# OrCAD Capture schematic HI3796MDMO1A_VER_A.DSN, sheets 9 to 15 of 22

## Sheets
9 SHEET_09: size Custom
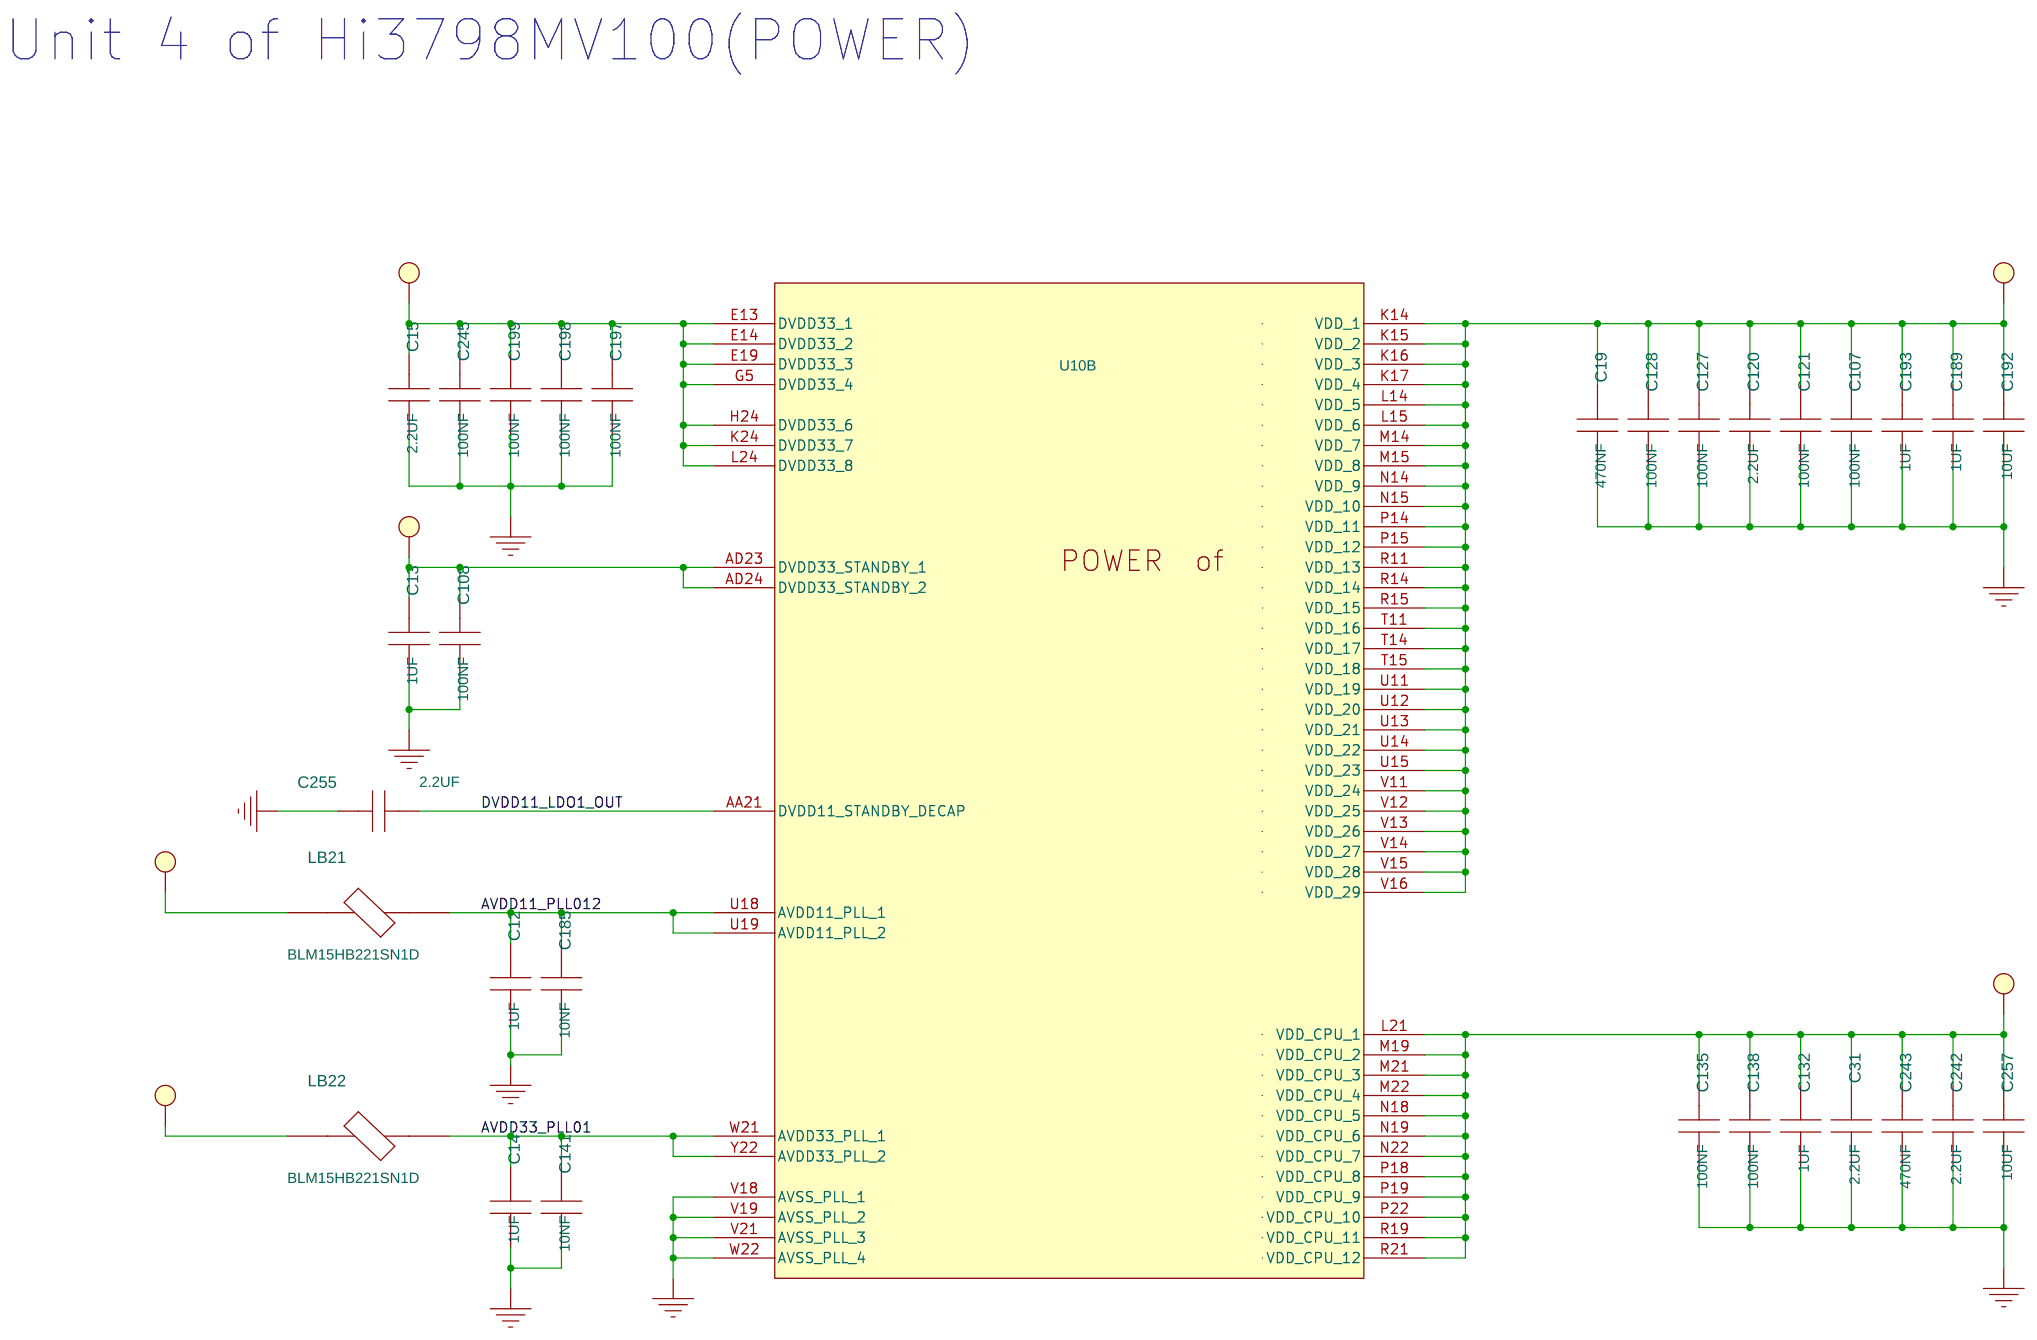
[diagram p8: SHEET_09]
10 SHEET_10: size B
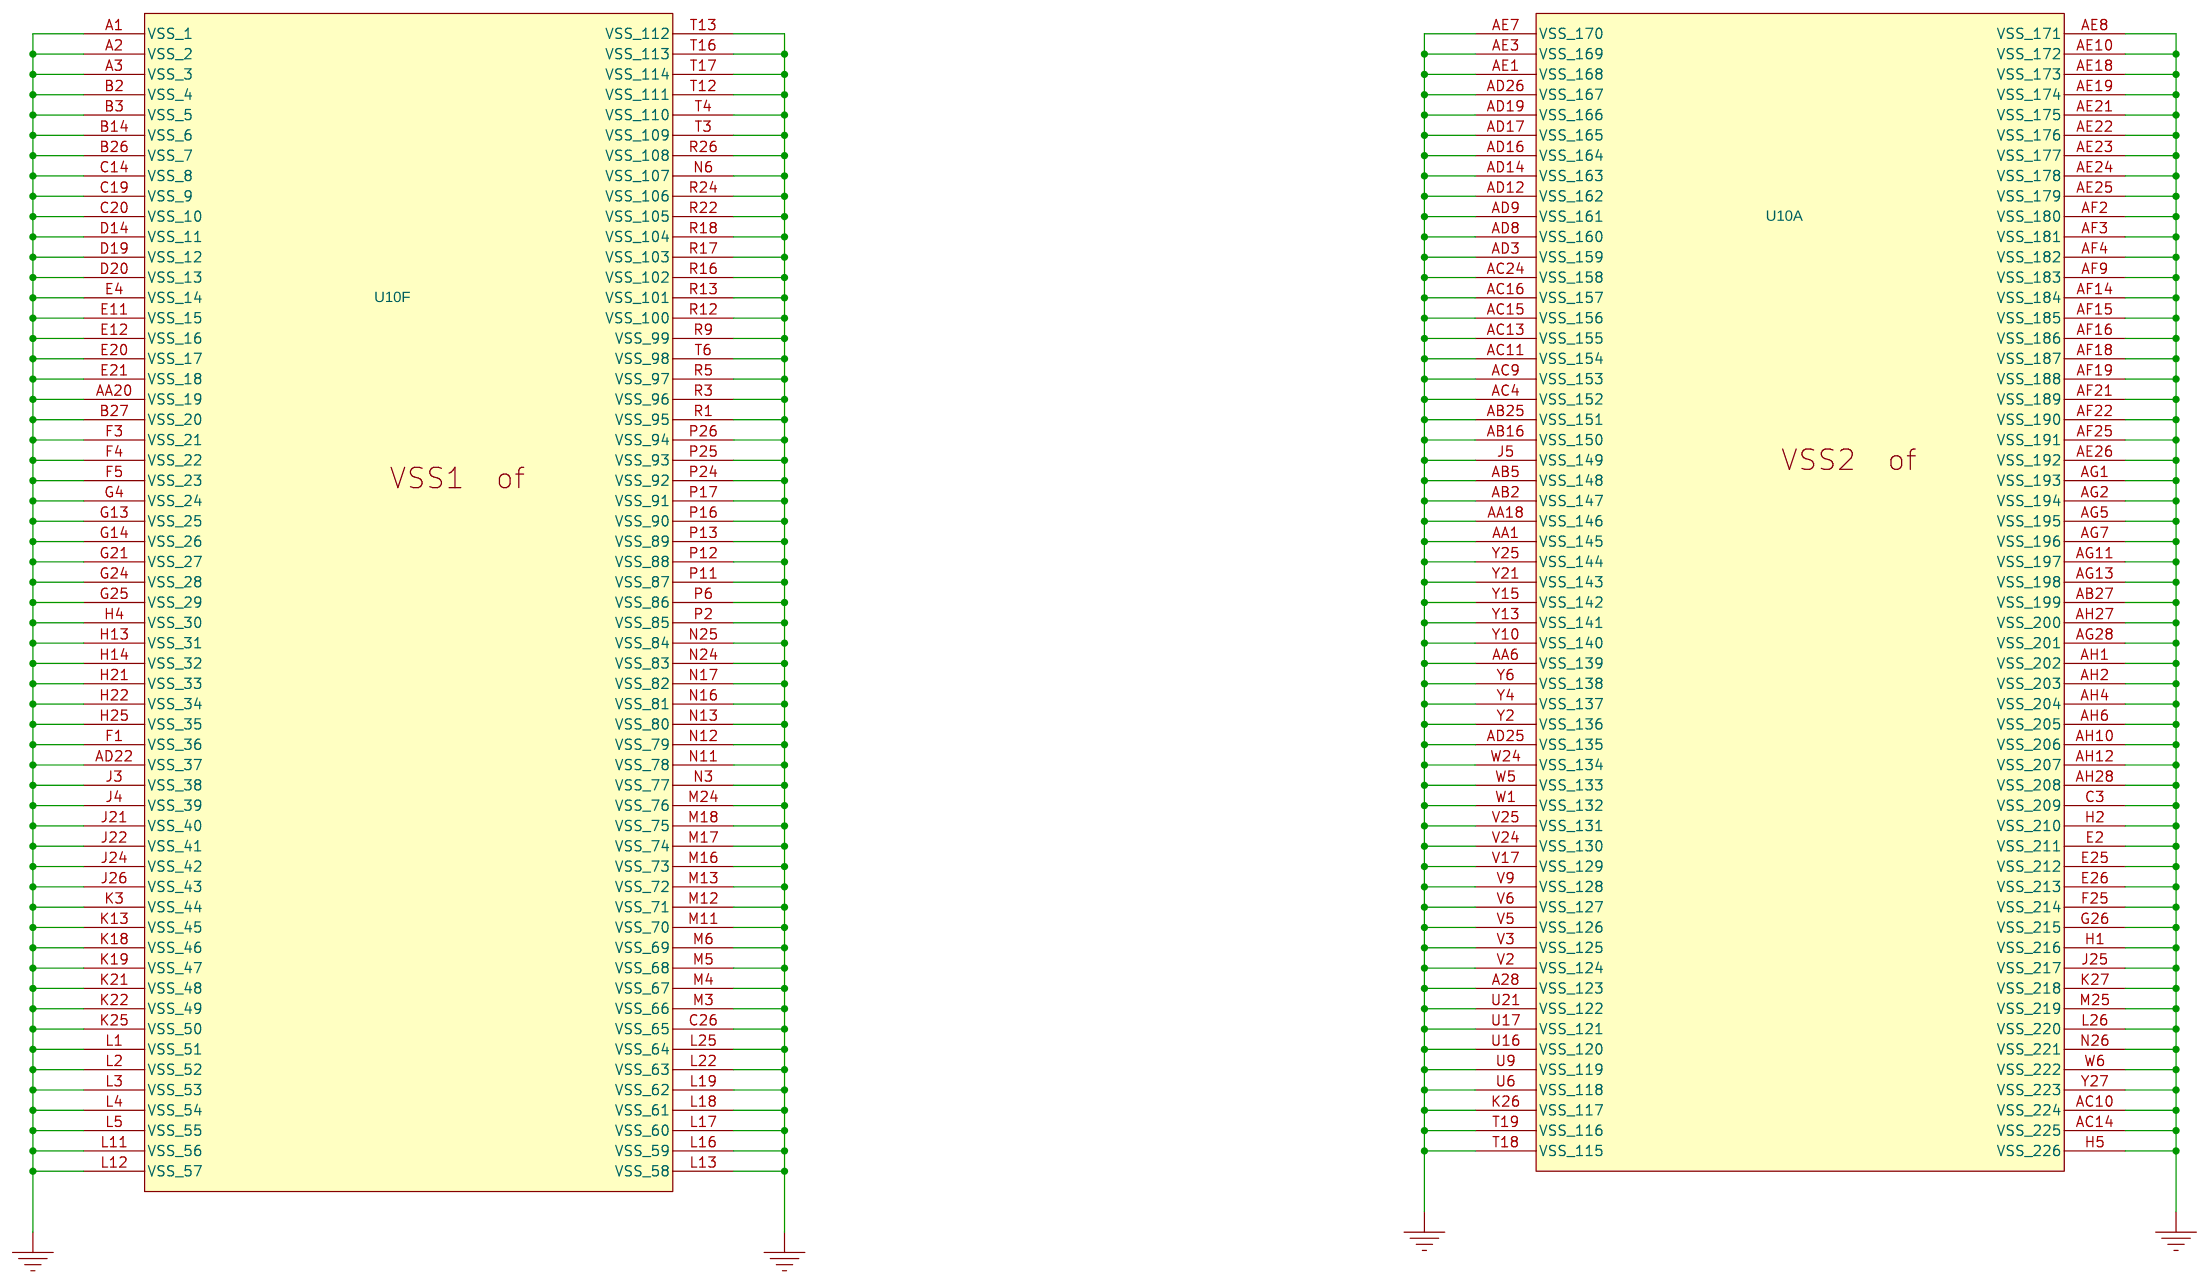
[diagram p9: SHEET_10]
11 SHEET_11: size Custom
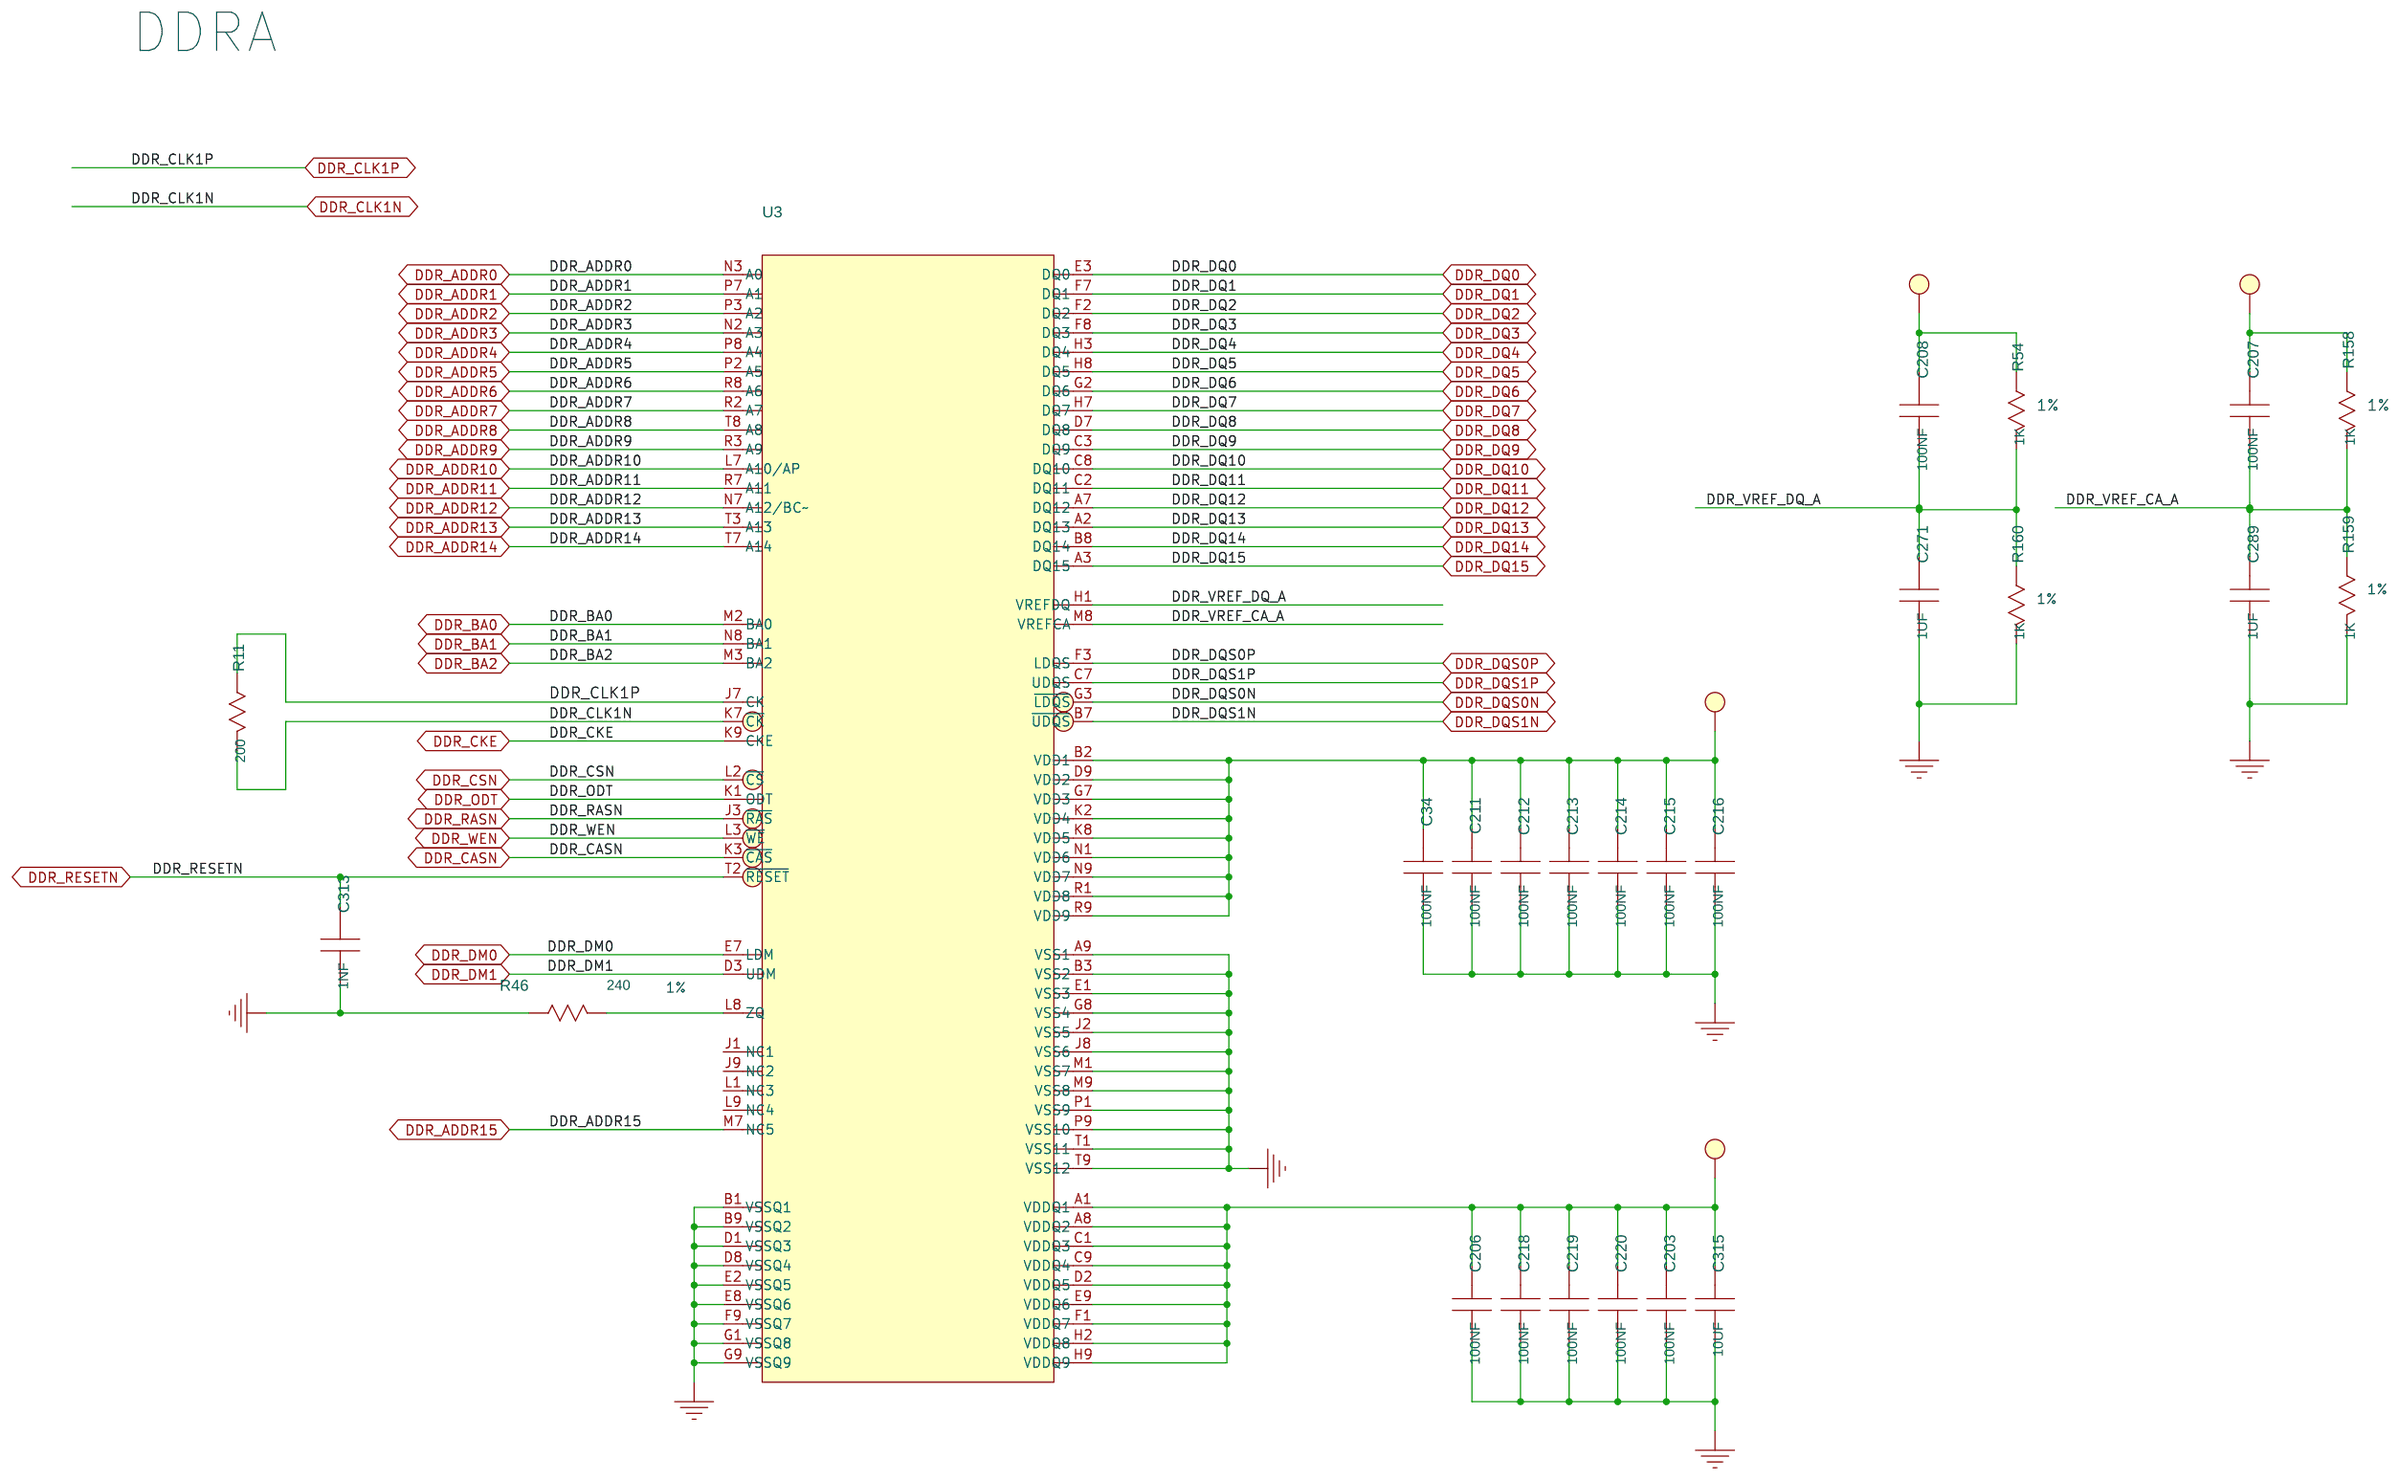
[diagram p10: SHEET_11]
12 SHEET_12: size B
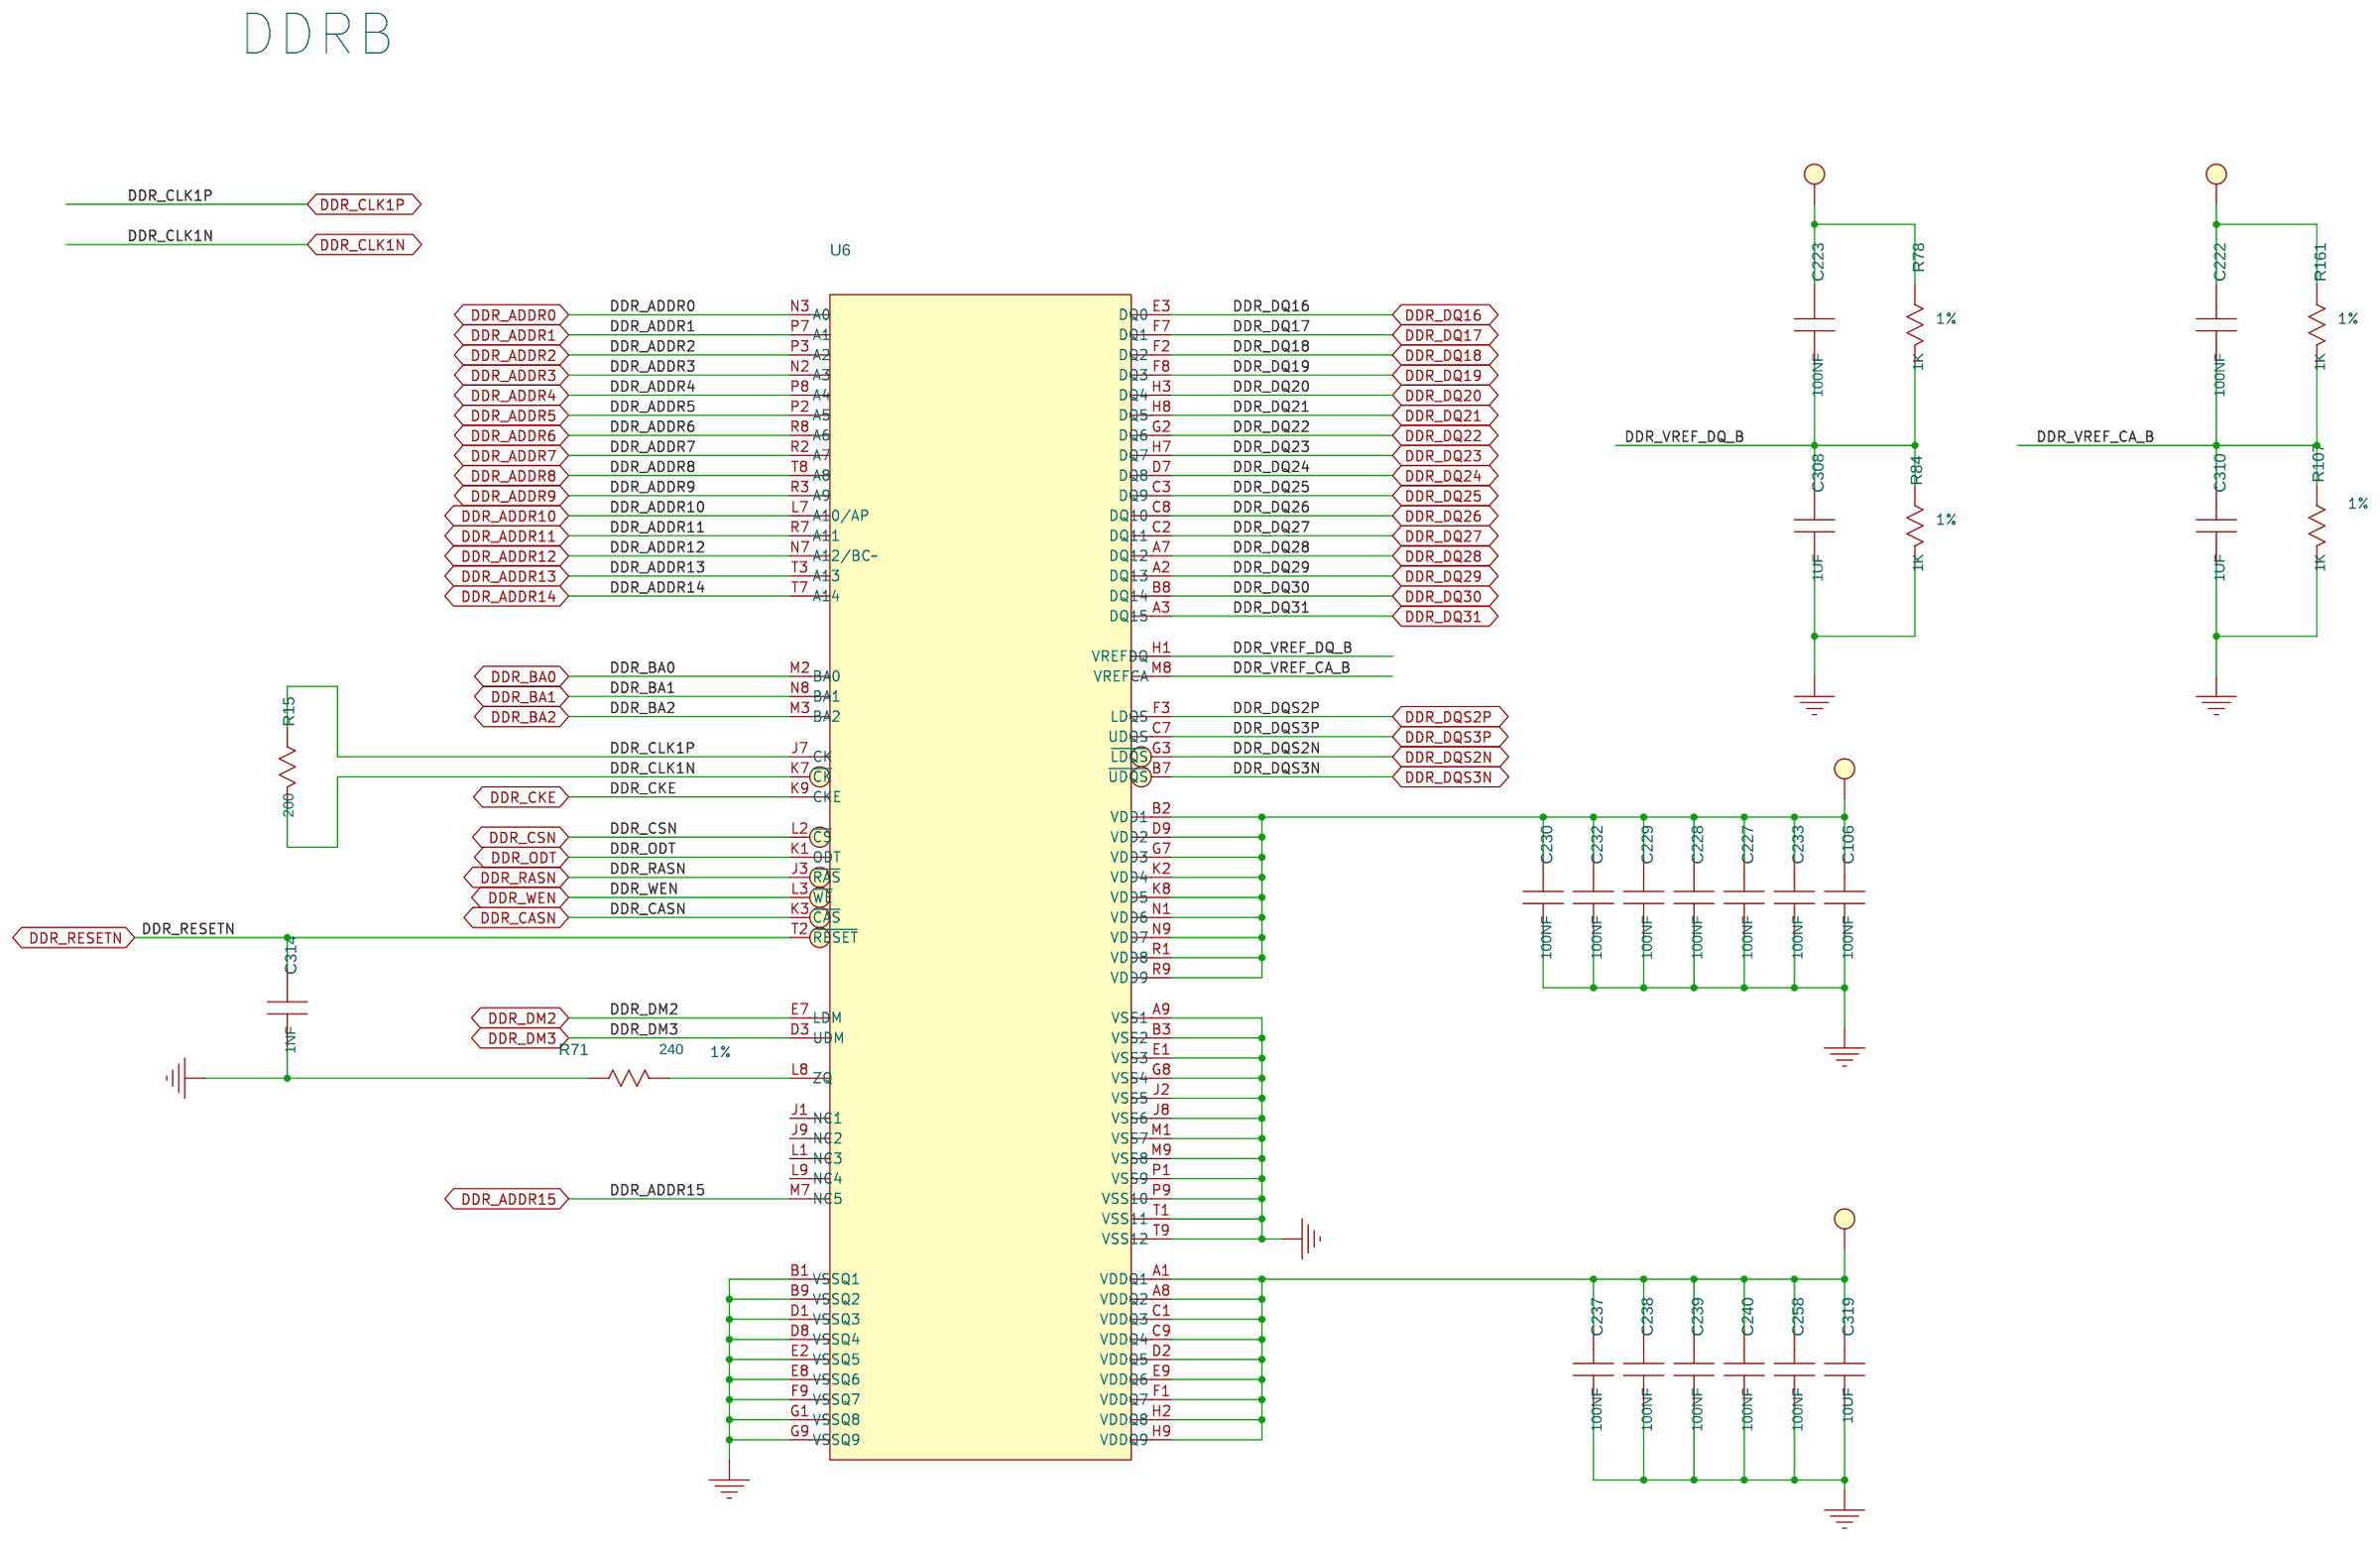
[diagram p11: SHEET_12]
13 SHEET_13: size Custom
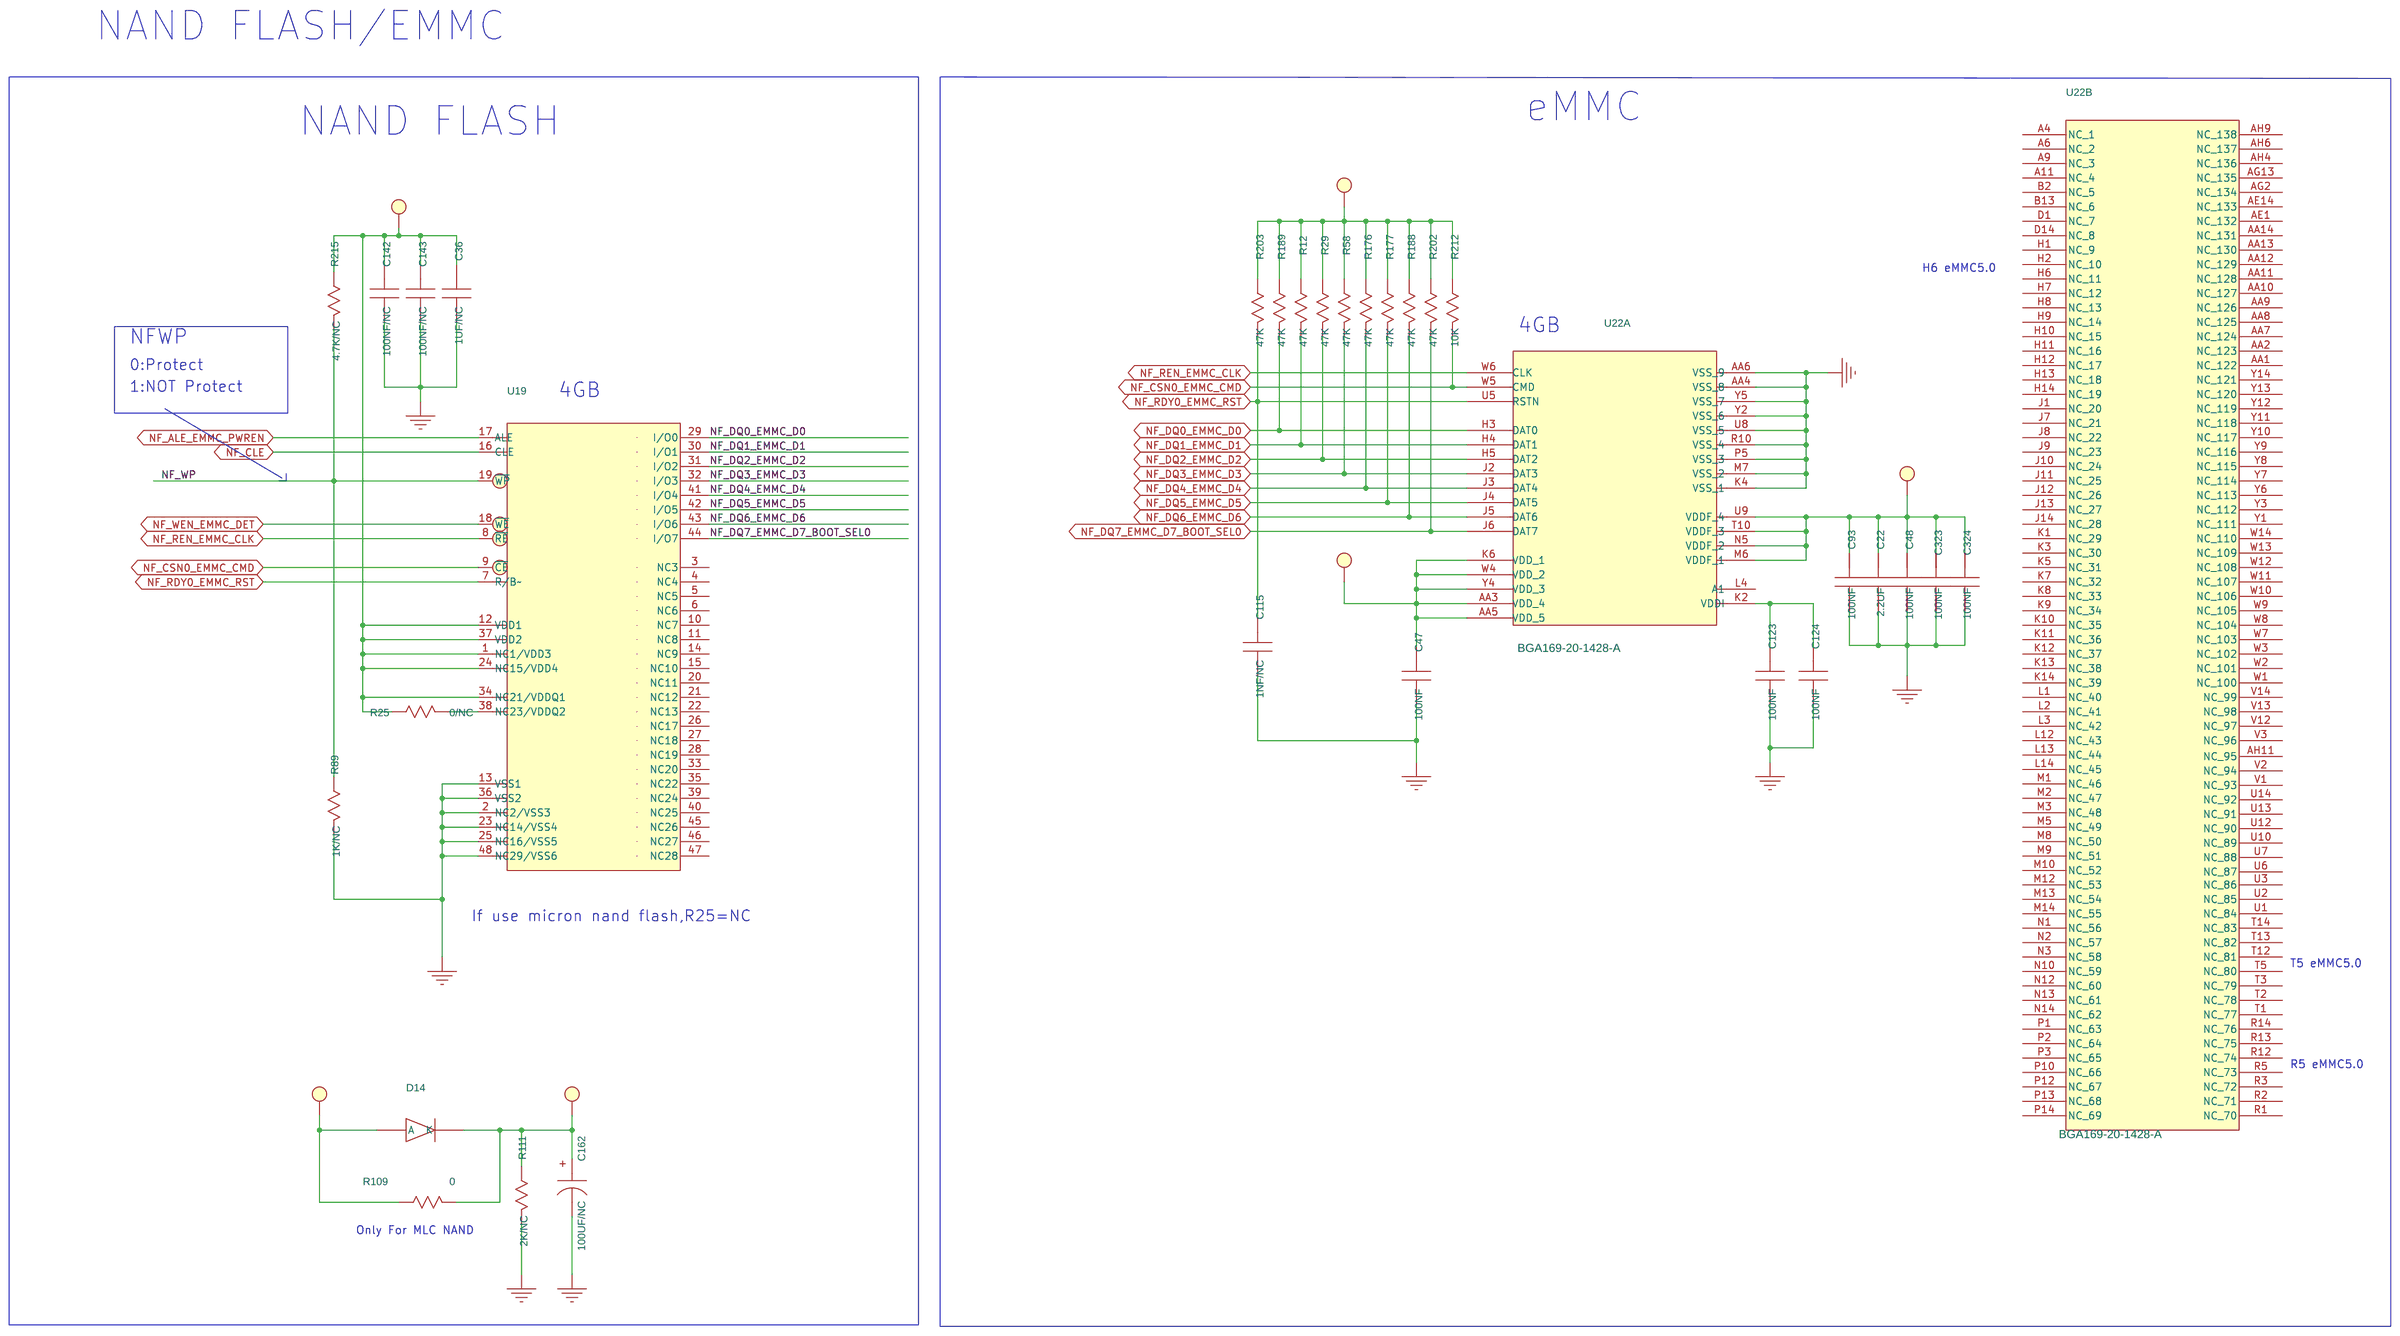
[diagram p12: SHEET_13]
14 SHEET_14: size Custom
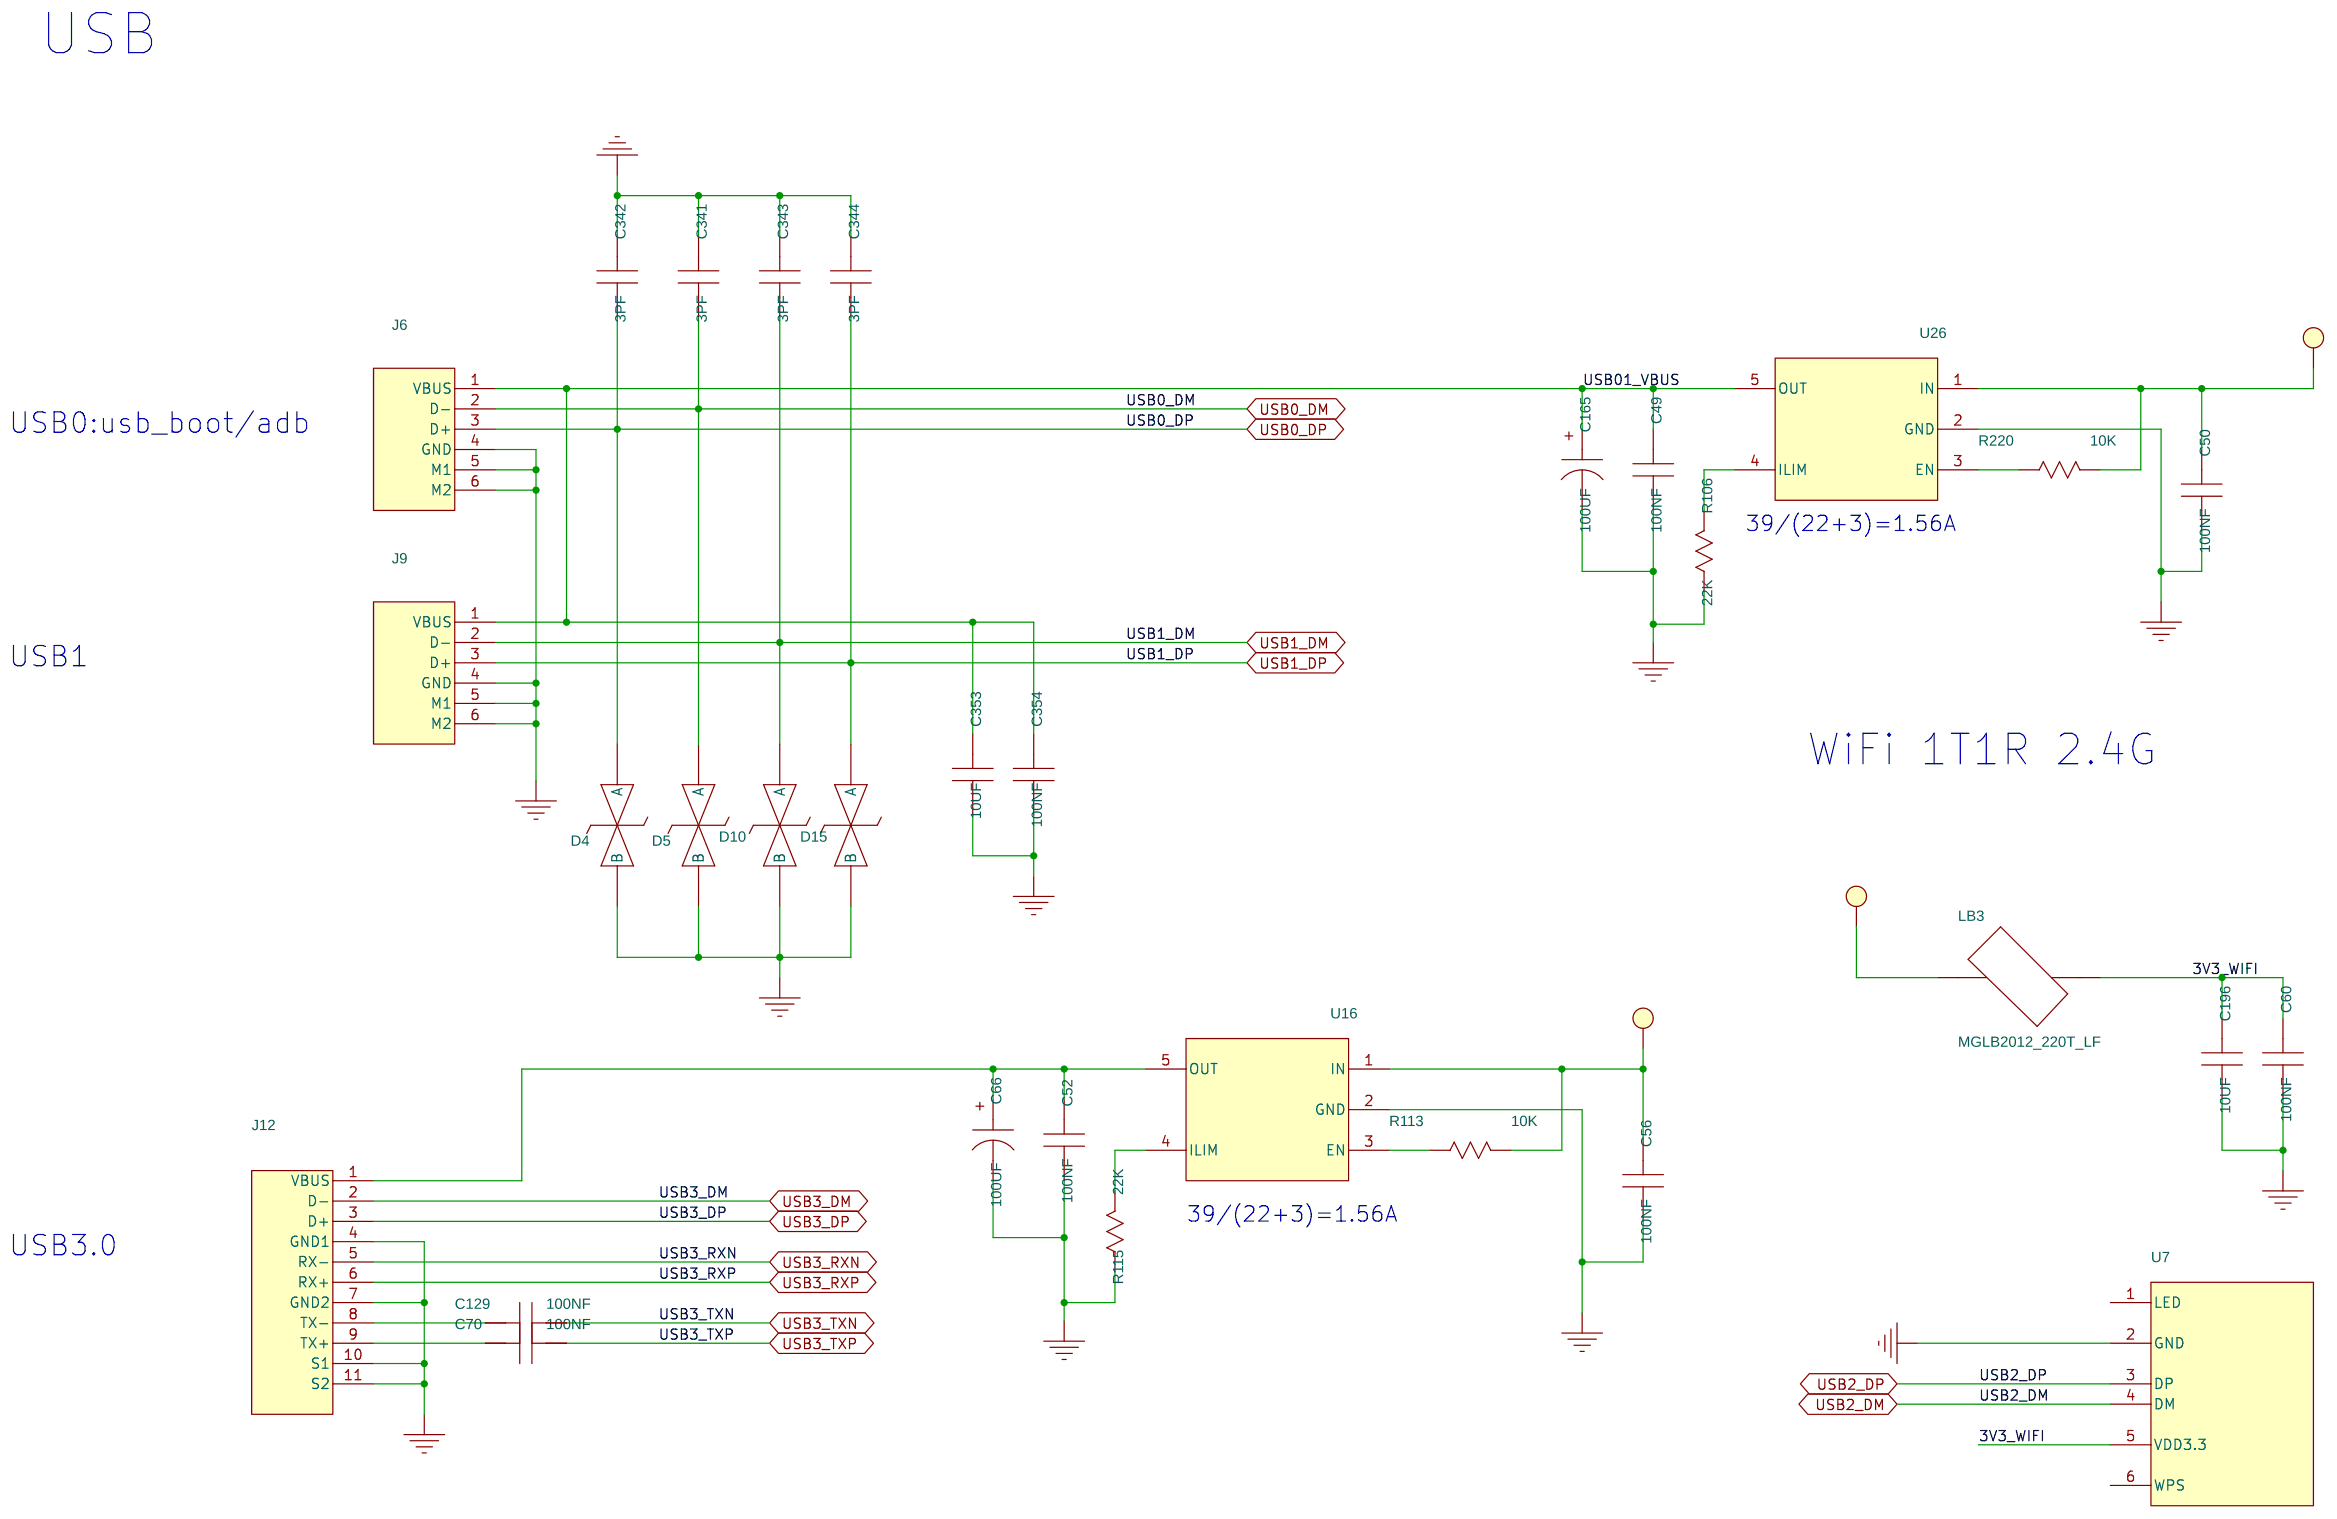
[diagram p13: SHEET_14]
15 SHEET_15: size Custom
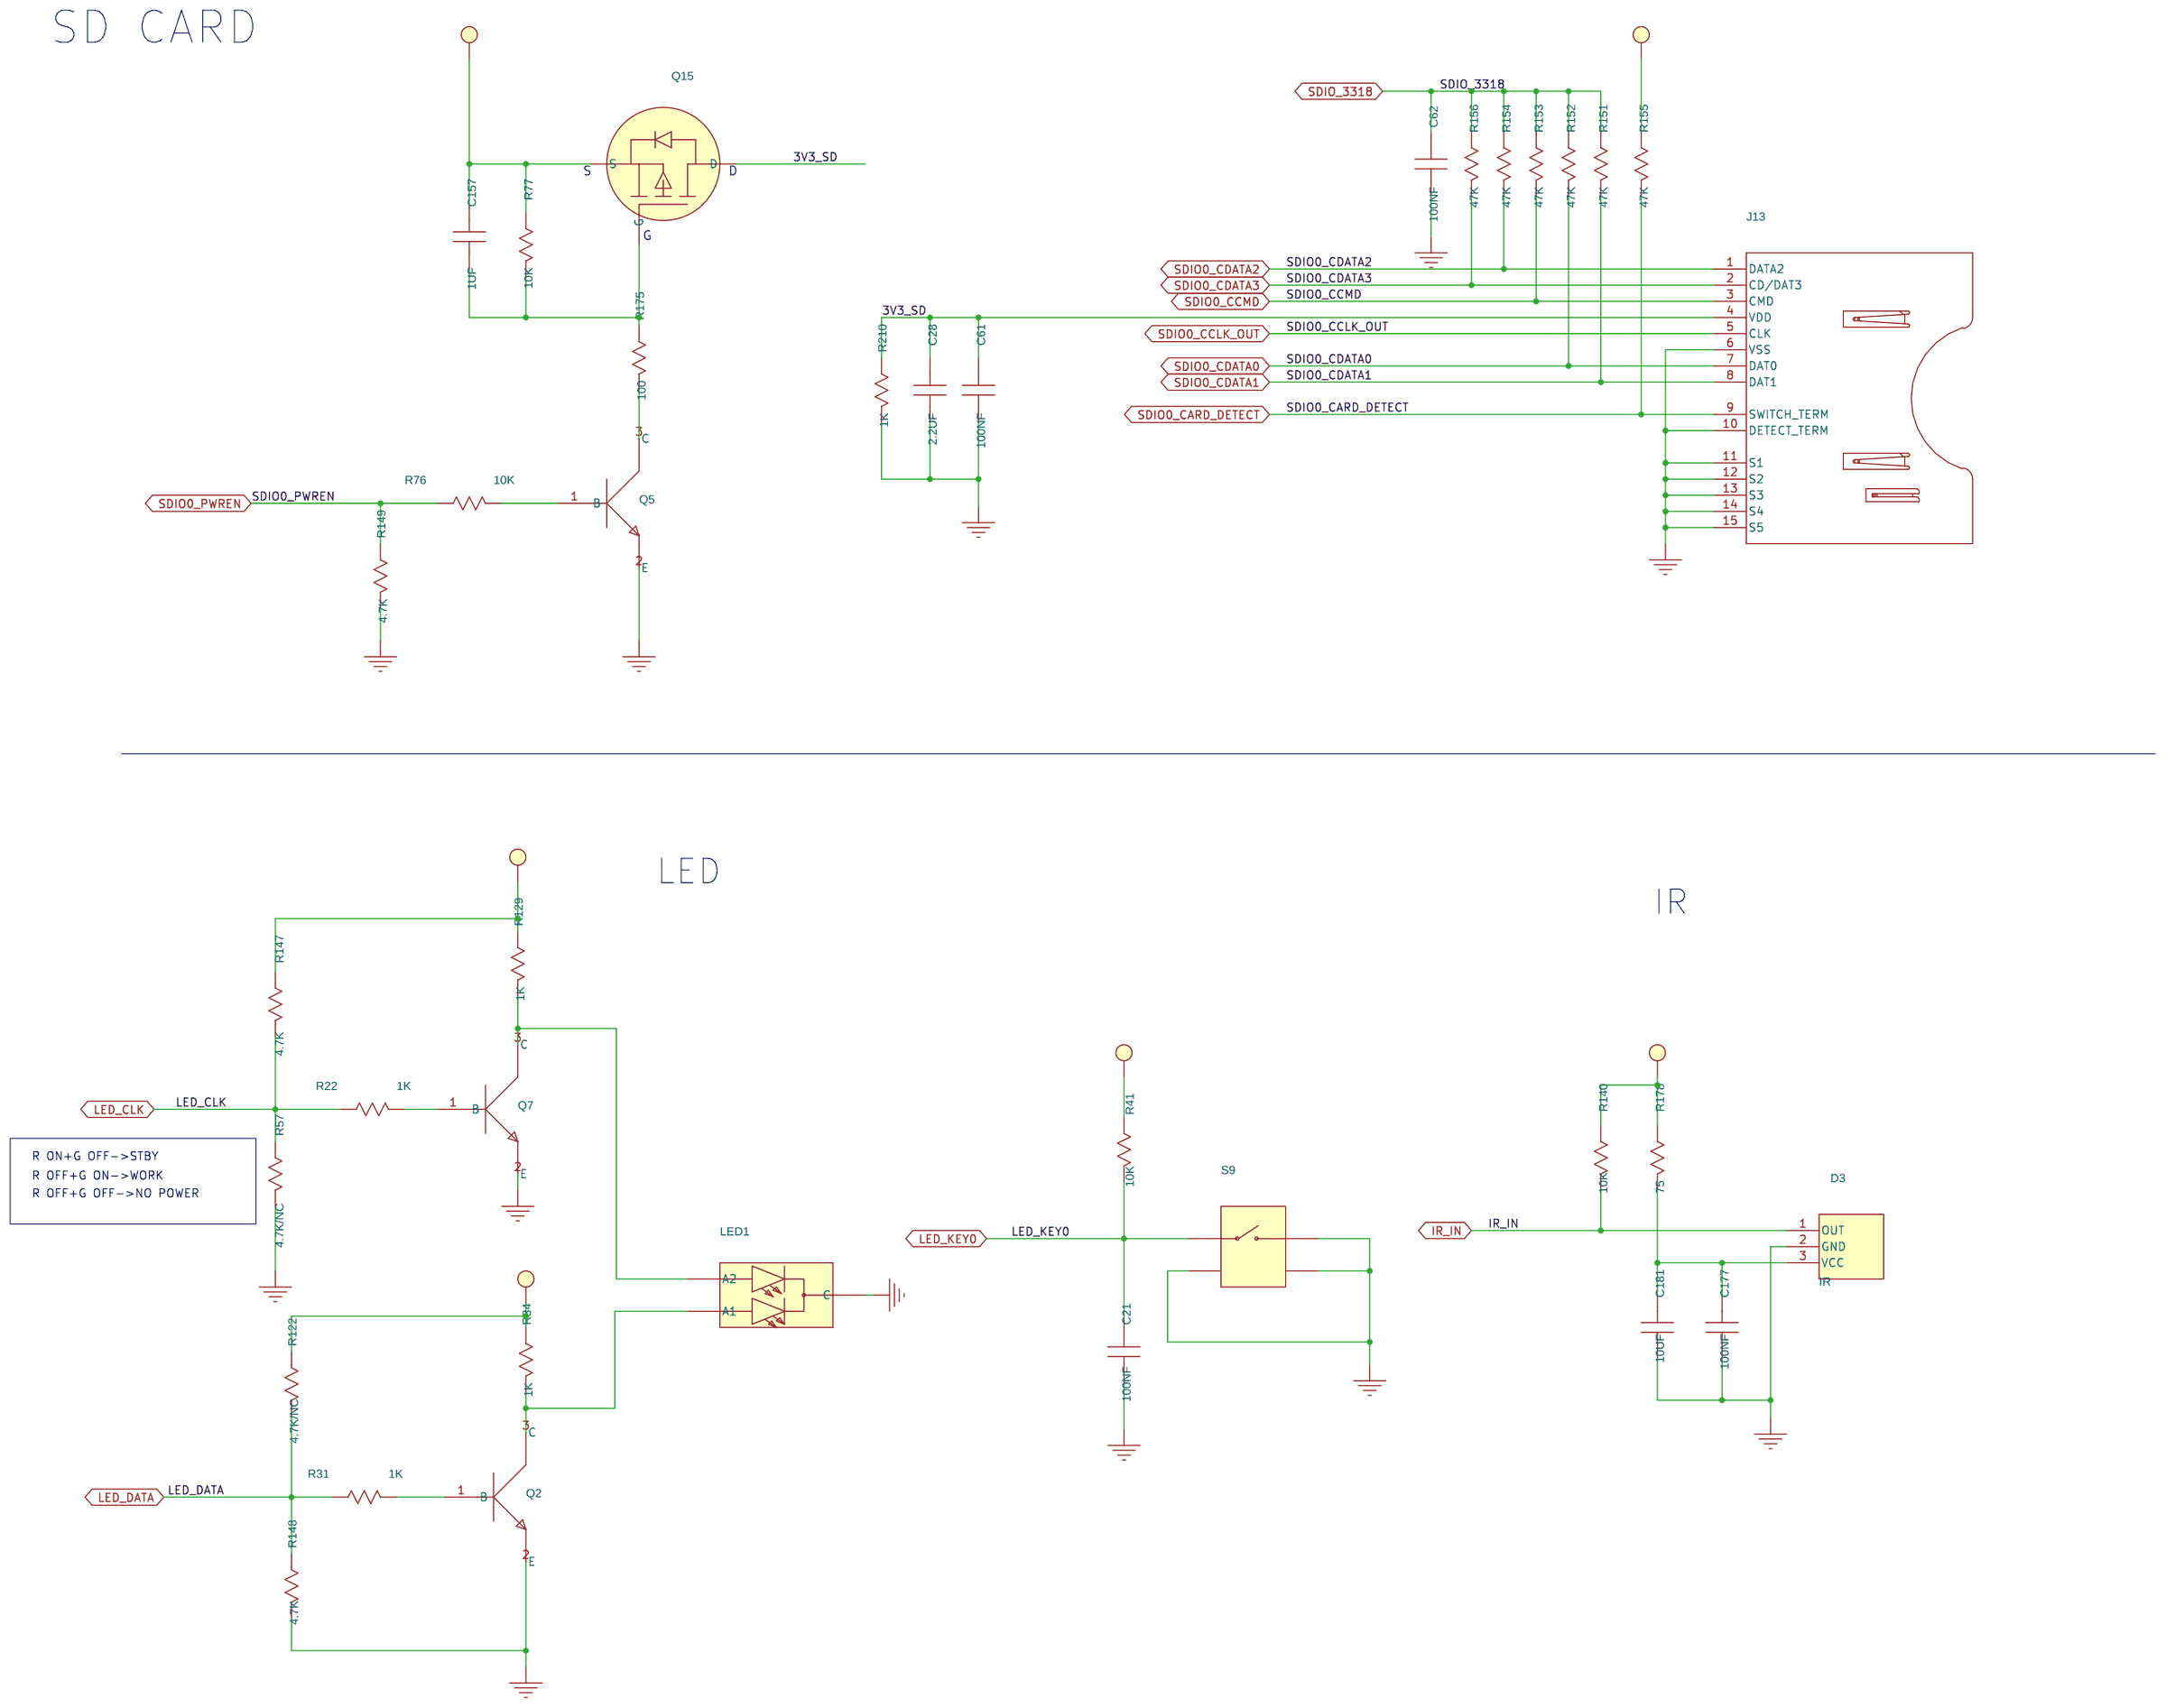
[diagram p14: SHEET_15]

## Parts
sheet SHEET_09
C12  1UF  [SC0402]
C13  1UF  [SC0402]
C14  1UF  [SC0402]
C15  2.2UF  [HSC0402]
C19  470NF  [SC0402]
C31  2.2UF  [HSC0402]
C107  100NF  [SC0402]
C108  100NF  [SC0402]
C120  2.2UF  [HSC0402]
C121  100NF  [SC0402]
C127  100NF  [SC0402]
C128  100NF  [SC0402]
C132  1UF  [SC0402]
C135  100NF  [SC0402]
C138  100NF  [SC0402]
C141  10NF  [SC0402]
C185  10NF  [SC0402]
C189  1UF  [SC0402]
C192  10UF  [SC0603]
C193  1UF  [SC0402]
C197  100NF  [SC0402]
C198  100NF  [SC0402]
C199  100NF  [SC0402]
C242  2.2UF  [HSC0402]
C243  470NF  [SC0402]
C245  100NF  [SC0402]
C255  2.2UF  [HSC0402]
C257  10UF  [SC0603]
LB21  LB  [SL0402]
LB22  LB  [SL0402]
sheet SHEET_10
U10  HI3796MV100  [PBGA573-32-27X27]  (sections A,B,C,D,E,F)
sheet SHEET_11
C34  100NF  [SC0402]
C203  100NF  [SC0402]
C206  100NF  [SC0402]
C207  100NF  [SC0402]
C208  100NF  [SC0402]
C211  100NF  [SC0402]
C212  100NF  [SC0402]
C213  100NF  [SC0402]
C214  100NF  [SC0402]
C215  100NF  [SC0402]
C216  100NF  [SC0402]
C218  100NF  [SC0402]
C219  100NF  [SC0402]
C220  100NF  [SC0402]
C271  1UF  [SC0402]
C289  1UF  [SC0402]
C313  1NF  [SC0402]
C315  10UF  [SC0805]
R11  200  [SR0402]
R46  240  [SR0402]
R54  1K  [SR0402]
R158  1K  [SR0402]
R159  1K  [SR0402]
R160  1K  [SR0402]
U3  MT41J256M16RE-15E-D  [BGA96-32-1609I]
sheet SHEET_12
C106  100NF  [SC0402]
C222  100NF  [SC0402]
C223  100NF  [SC0402]
C227  100NF  [SC0402]
C228  100NF  [SC0402]
C229  100NF  [SC0402]
C230  100NF  [SC0402]
C232  100NF  [SC0402]
C233  100NF  [SC0402]
C237  100NF  [SC0402]
C238  100NF  [SC0402]
C239  100NF  [SC0402]
C240  100NF  [SC0402]
C258  100NF  [SC0402]
C308  1UF  [SC0402]
C310  1UF  [SC0402]
C314  1NF  [SC0402]
C319  10UF  [SC0805]
R15  200  [SR0402]
R71  240  [SR0402]
R78  1K  [SR0402]
R84  1K  [SR0402]
R107  1K  [SR0402]
R161  1K  [SR0402]
U6  MT41J256M16RE-15E-D  [BGA96-32-1609I]
sheet SHEET_13
C22  2.2UF  [HSC0402]
C36  1UF/NC  [SC0402]
C47  100NF  [SC0402]
C48  100NF  [SC0402]
C93  100NF  [SC0402]
C115  1NF/NC  [SC0402]
C123  100NF  [SC0402]
C124  100NF  [SC0402]
C142  100NF/NC  [SC0402]
C143  100NF/NC  [SC0402]
C162  100UF/NC  [SAC6666]
C323  100NF  [SC0402]
C324  100NF  [SC0402]
D14  NC  [HSOD323A]
R12  47K  [SR0402]
R25  0/NC  [SR0402]
R29  47K  [SR0402]
R58  47K  [SR0402]
R89  1K/NC  [SR0402]
R109  0  [SR1206]
R111  2K/NC  [SR0603]
R176  47K  [SR0402]
R177  47K  [SR0402]
R188  47K  [SR0402]
R189  47K  [SR0402]
R202  47K  [SR0402]
R203  47K  [SR0402]
R212  10K  [SR0402]
R215  4.7K/NC  [SR0402]
U19  NC  [SOP48-20-720B]
U22  EMMC  [BGA169-20-1428-A]  (sections A,B)
sheet SHEET_14
C49  100NF  [SC0402]
C50  100NF  [SC0402]
C52  100NF  [SC0402]
C56  100NF  [SC0402]
C60  100NF  [SC0402]
C66  100UF  [SAC6666]
C70  100NF  [SC0402]
C129  100NF  [SC0402]
C165  100UF  [SAC6666]
C196  10UF  [SC0603]
C341  3PF  [SC0402]
C342  3PF  [SC0402]
C343  3PF  [SC0402]
C344  3PF  [SC0402]
C353  10UF  [SC0805]
C354  100NF  [SC0402]
D4  NC  [SC0402]
D5  NC  [SC0402]
D10  NC  [SC0402]
D15  NC  [SC0402]
J6  USB-4  [USB4-1415]
J9  USB-4  [USB4-1415]
J12  SIP7S2  [USB3_0_9P_DIP_MAINSUPER]
LB3  LB  [SL0805]
R106  22K  [SR0402]
R113  10K  [SR0402]
R115  22K  [SR0402]
R220  10K  [SR0402]
U7  RL_8188EUS  [RL_8188EUS]
U16  ETA6010  [SOT23-5]
U26  ETA6010  [SOT23-5]
sheet SHEET_15
C21  100NF  [SC0603]
C28  2.2UF  [HSC0402]
C61  100NF  [SC0402]
C62  100NF  [SC0402]
C157  1UF  [SC0402]
C177  100NF  [SC0402]
C181  10UF  [SC0603]
D3  IR  [SEN3-100C]
J13  MMC10S5  [SDC10-1415]
LED1  NC  [LED3C-100C]
Q2  NPN-BEC  [SOT23]
Q5  NPN-BEC  [SOT23]
Q7  NPN-BEC  [SOT23]
Q15  PMOS-GSD  [SOT23]
R22  1K  [SR0402]
R31  1K  [SR0402]
R34  1K  [SR0402]
R41  10K  [SR0402]
R57  4.7K/NC  [SR0402]
R76  10K  [SR0603]
R77  10K  [SR0603]
R122  4.7K/NC  [SR0402]
R129  1K  [SR0402]
R140  10K  [SR0402]
R147  4.7K  [SR0402]
R148  4.7K  [SR0402]
R149  4.7K  [SR0603]
R151  47K  [SR0402]
R152  47K  [SR0402]
R153  47K  [SR0402]
R154  47K  [SR0402]
R155  47K  [SR0402]
R156  47K  [SR0402]
R175  100  [SR0603]
R178  75  [SR0402]
R210  1K  [SR0603]
S9  NC  [TSW4-RG-C]

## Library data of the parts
C12-C14 C36 C132 C157 C189 C193 = C_0: %182%%238%%182%%168%%185%%164%%215%%247%%181%%231%%209%%185%(V): 10; %195%%232%%202%%246%: SMD陶瓷电容-10V-1000NF-+/-10%-X5R-0402-BT,TS16949; %208%%161%%192%%224%%195%%251%%179%%198%: SMD陶瓷电容; CODE: 8070612; COMPONENT_HIGH_MAX: 0.55MM; DEVICE: CV05X5R105K10AH
C15 C22 C28 C31 C120 C242 C255 = C_0: %182%%238%%182%%168%%185%%164%%215%%247%%181%%231%%209%%185%(V): 6.3; %195%%232%%202%%246%: SMD陶瓷电容-6.3V-2200NF-+/-20%-X5R-0402-TS16949; %208%%161%%192%%224%%195%%251%%179%%198%: SMD陶瓷电容; CODE: 8070667; COMPONENT_HIGH_MAX: 0.6MM; DEVICE: GRM155R60J225ME15D
C19 C243 = C_0: %182%%238%%182%%168%%185%%164%%215%%247%%181%%231%%209%%185%(V): 6.3; %195%%232%%202%%246%: SMD陶瓷电容-6.3V-470NF-+/-10%-X5R-0402; %208%%161%%192%%224%%195%%251%%179%%198%: SMD陶瓷电容; CODE: 8070625; COMPONENT_HIGH_MAX: 0.55MM; DEVICE: GRM155R60J474KE19D
C34 C47-C50 C52 C56 C60-C62 C70 C93 C106-C108 C121 C123 C124 C127-C129 C135 C138 C197-C199 C203 C206-C208 C211-C216 C218-C220 C222 C223 C227-C230 C232 C233 C237-C240 C245 C258 C271 C289 C308 C310 C323 C324 C354 = C_0: %182%%238%%182%%168%%185%%164%%215%%247%%181%%231%%209%%185%(V): 10; %195%%232%%202%%246%: SMD陶瓷电容-10V-100NF-+/-10%-X5R-0402; %208%%161%%192%%224%%195%%251%%179%%198%: SMD陶瓷电容; CODE: 8070561; COMPONENT_HIGH_MAX: 0.55MM; DEVICE: C0402C104K8PAC_7867
C141 C185 = C_0: %182%%238%%182%%168%%185%%164%%215%%247%%181%%231%%209%%185%(V): 16; %195%%232%%202%%246%: SMD陶瓷电容-16V-10NF-+/-10%-X7R-0402-BT,TS16949; %208%%161%%192%%224%%195%%251%%179%%198%: SMD陶瓷电容; CODE: 8070449; COMPONENT_HIGH_MAX: 0.55MM; DEVICE: GRM155R71C103KA01D
C181 C192 C196 C257 = C_0: %182%%238%%182%%168%%185%%164%%215%%247%%181%%231%%209%%185%(V): 6.3; %195%%232%%202%%246%: SMD陶瓷电容-6.3V-10000NF-+/-20%-X5R-0603-BT,TS16949; %208%%161%%192%%224%%195%%251%%179%%198%: SMD陶瓷电容; CODE: 8070649; COMPONENT_HIGH_MAX: 0.9MM; DEVICE: C1608X5R0J106MT0A0E
LB21 LB22 = LB: %182%%238%%182%%168%%181%%231%%193%%247%: 0.25; %195%%232%%202%%246%: EMI磁珠-25%-220OHM-1OHM-0.25A-0402-900OHM TYP@1GHZ; %208%%161%%192%%224%%195%%251%%179%%198%: EMI磁珠; CODE: 10070030; COMPONENT_HIGH_MAX: 0.06MM; DEVICE: BLM15HB221SN1D
U10 = HI3796MV100
C115 C313 C314 = C_0: %182%%238%%182%%168%%185%%164%%215%%247%%181%%231%%209%%185%(V): 50; %195%%232%%202%%246%: SMD陶瓷电容-50V-1NF-+/-10%-X7R-0402-BT; %208%%161%%192%%224%%195%%251%%179%%198%: SMD陶瓷电容; CODE: 8070531; COMPONENT_HIGH_MAX: 0.56MM; DEVICE: 04025C102KAT2A
C315 C319 = C_0: %182%%238%%182%%168%%185%%164%%215%%247%%181%%231%%209%%185%(V): 6.3; %195%%232%%202%%246%: SMD陶瓷电容-6.3V-10000NF-+/-10%-X5R-0805-TS16949; %208%%161%%192%%224%%195%%251%%179%%198%: SMD陶瓷电容; CODE: 8070565; COMPONENT_HIGH_MAX: 1.45MM; DEVICE: CEJMK212BJ106KD_T
R11 R15 = R_0: %182%%238%%182%%168%%185%%166%%194%%202%(W): 0.06; %195%%232%%202%%246%: 片式厚膜电阻器-0.0625W-200OHM-+/-5%-0402-BT; %208%%161%%192%%224%%195%%251%%179%%198%: 片式厚膜电阻器; %215%%232%%214%%181%%212%%202%%208%%237%%198%%171%%178%%238%: +/-5%; CODE: 7090863; COMPONENT_HIGH_MAX: 0.4MM; DEVICE: RK73B1ETTP201J
R46 R71 = R_0: %182%%238%%182%%168%%185%%166%%194%%202%(W): 0.06; %195%%232%%202%%246%: 片式厚膜电阻器-0.0625W-240OHM-+/- 1%-0402-BT; %208%%161%%192%%224%%195%%251%%179%%198%: 片式厚膜电阻器; %215%%232%%214%%181%%212%%202%%208%%237%%198%%171%%178%%238%: +/- 1%; CODE: 7091782; COMPONENT_HIGH_MAX: 0.4MM; DEVICE: RC0402FR_07240RL
R54 R78 R84 R107 R158-R161 = R_0: %182%%238%%182%%168%%185%%166%%194%%202%(W): 0.06; %195%%232%%202%%246%: 片式厚膜电阻器-0.0625W-1000OHM-+/-1%-0402-BT; %208%%161%%192%%224%%195%%251%%179%%198%: 片式厚膜电阻器; %215%%232%%214%%181%%212%%202%%208%%237%%198%%171%%178%%238%: +/-1%; CODE: 7091282; COMPONENT_HIGH_MAX: 0.4MM; DEVICE: RC0402FR_071KL
U3 U6 = MT41J256M16RE-15E-D_1: %195%%232%%202%%246%: DDR3 DRAM-4GBIT-800MHZ-16BIT-1.5V-FBGA96(无铅); %208%%161%%192%%224%%195%%251%%179%%198%: DDR3 DRAM; CODE: 40020173; COMPONENT_HIGH_MAX: -99999999MM; DEVICE: H5TQ4G63MFR_PBC_A
C142 C143 = C_0: %182%%238%%182%%168%%185%%164%%215%%247%%181%%231%%209%%185%(V): 16; %195%%232%%202%%246%: SMD陶瓷电容-16V-100NF-±10%-X7R-0402; %208%%161%%192%%224%%195%%251%%179%%198%: SMD陶瓷电容; CODE: 8070614; COMPONENT_HIGH_MAX: 0.6MM; DEVICE: RMEMK105BJ104KV_FR
C66 C162 C165 = CP_1: %182%%238%%182%%168%%185%%164%%215%%247%%181%%231%%209%%185%(V): 16; %195%%232%%202%%246%: 非固体SMD铝电容-16V-100UF-+/-20%-6.3*5.4MM-极性-105DEGC-1000H-片式,温度敏感器件-工艺耐温250DEGC,5S; %208%%161%%192%%224%%195%%251%%179%%198%: 非固体SMD铝电容; CODE: 8010269; COMPONENT_HIGH_MAX: 5.7MM; DEVICE: UWT1C101MCL1GB
D14 = D_A: %195%%232%%202%%246%: 肖特基二极管-10V-3A-0.24V-SOD323-BT; %208%%161%%192%%224%%195%%251%%179%%198%: 肖特基二极管; CODE: 15010252; COMPONENT_HIGH_MAX: 1.1MM; DEVICE: BAT60BE6327
R12 R29 R58 R151-R156 R176 R177 R188 R189 R202 R203 = R_0: %182%%238%%182%%168%%185%%166%%194%%202%(W): 0.06; %195%%232%%202%%246%: 片式厚膜电阻器-0.0625W-47000OHM-+/-5%-0402-ELOM; %208%%161%%192%%224%%195%%251%%179%%198%: 片式厚膜电阻器; %215%%232%%214%%181%%212%%202%%208%%237%%198%%171%%178%%238%: +/-5%; CODE: 7090819; DEVICE: RC0402JR_0747K
R25 = R_0: %182%%238%%182%%168%%185%%166%%194%%202%(W): 0.06; %195%%232%%202%%246%: 片式厚膜电阻器-0.0625W-0OHM-< 50MOHM-0402-1A-BT; %208%%161%%192%%224%%195%%251%%179%%198%: 片式厚膜电阻器; %215%%232%%214%%181%%212%%202%%208%%237%%198%%171%%178%%238%: < 50MOHM; CODE: 7090800; DEVICE: RC0402JR_070R
R89 = R_0: %182%%238%%182%%168%%185%%166%%194%%202%(W): 0.06; %195%%232%%202%%246%: 片式厚膜电阻器-0.0625W-1000OHM-±5%-0402; %208%%161%%192%%224%%195%%251%%179%%198%: 片式厚膜电阻器; %215%%232%%214%%181%%212%%202%%208%%237%%198%%171%%178%%238%: ±5%; CODE: 7090809; COMPONENT_HIGH_MAX: 0.4MM; DEVICE: RC0402JR_071KL
R109 = R_0: %182%%238%%182%%168%%185%%166%%194%%202%(W): 0.25; %195%%232%%202%%246%: 片式厚膜电阻器-0.25W-0OHM-<50MOHM-1206-2A-BT; %208%%161%%192%%224%%195%%251%%179%%198%: 片式厚膜电阻器; %215%%232%%214%%181%%212%%202%%208%%237%%198%%171%%178%%238%: <50MOHM; CODE: 7090002; COMPONENT_HIGH_MAX: 0.7MM; DEVICE: RC1206JR_070RL
R111 = R_0: %182%%238%%182%%168%%185%%166%%194%%202%(W): 0.1; %195%%232%%202%%246%: 片式厚膜电阻器-0.1W-2000OHM-+/-5%-0603; %208%%161%%192%%224%%195%%251%%179%%198%: 片式厚膜电阻器; %215%%232%%214%%181%%212%%202%%208%%237%%198%%171%%178%%238%: +/-5%; CODE: 7090643; COMPONENT_HIGH_MAX: 0.55MM; DEVICE: RC0603JR_072K
R113 R212 R220 = R_0: %182%%238%%182%%168%%185%%166%%194%%202%(W): 0.06; %195%%232%%202%%246%: 片式厚膜电阻器-0.0625W-10000OHM-+/-5%-0402-BT; %208%%161%%192%%224%%195%%251%%179%%198%: 片式厚膜电阻器; %215%%232%%214%%181%%212%%202%%208%%237%%198%%171%%178%%238%: +/-5%; CODE: 7090815; DEVICE: RC_02W103JT
R215 = R_0: %182%%238%%182%%168%%185%%166%%194%%202%(W): 0.06; %195%%232%%202%%246%: 片式厚膜电阻器-0.0625W-4700OHM-+/-5%-0402; %208%%161%%192%%224%%195%%251%%179%%198%: 片式厚膜电阻器; %215%%232%%214%%181%%212%%202%%208%%237%%198%%171%%178%%238%: +/-5%; CODE: 7090793; COMPONENT_HIGH_MAX: 0.4MM; DEVICE: RK73B1ELTP472J
U19 = MLC_NAND_0: CODE: *; DEVICE: NAND
U22 = M_0: CODE: 40060446; CaptureCellPackProp: MA
C341-C344 = C_0: %182%%238%%182%%168%%185%%164%%215%%247%%181%%231%%209%%185%(V): 50; %195%%232%%202%%246%: SMD陶瓷电容-50V-0.003NF-+/-0.25PF-NPO-0402; %208%%161%%192%%224%%195%%251%%179%%198%: SMD陶瓷电容; CODE: 8070636; COMPONENT_HIGH_MAX: 0.55MM; DEVICE: GRM1555C1H3R0CZ01D
C353 = C_0: %182%%238%%182%%168%%185%%164%%215%%247%%181%%231%%209%%185%(V): 25; %195%%232%%202%%246%: SMD陶瓷电容-25V-10000NF-+/-20%-X5R-0805; %208%%161%%192%%224%%195%%251%%179%%198%: SMD陶瓷电容; CODE: 8071629; COMPONENT_HIGH_MAX: 1.45MM; DEVICE: C2012X5R1E106KT000N1
D4 D5 D10 D15 = ULCE0505A015FR
J6 J9 = USB-4: %195%%232%%202%%246%: 网口连接器-单排-单端口-4PIN-4BIT-屏蔽-USB A型插座/侧面插入型-引脚长3.2MM-THT; %208%%161%%192%%224%%195%%251%%179%%198%: 网口连接器; CODE: 14080105; COMPONENT_HIGH_MAX: 7.12MM; DEVICE: 292303_1
J12 = SIP7S2: DEVICE: USB3_ATYPE
LB3 = LB_v2: %195%%232%%202%%246%: EMI磁珠-+/-25%-220OHM-0.05OHM-2A-0805; %208%%161%%192%%224%%195%%251%%179%%198%: EMI磁珠; CODE: 10070012; COMPONENT_HIGH_MAX: 1.05MM; DEVICE: MGLB2012_220T_LF
R106 R115 = R_0: %182%%238%%182%%168%%185%%166%%194%%202%(W): 0.06; %195%%232%%202%%246%: 片式厚膜电阻器-0.0625W-22000OHM-+/-1%-0402; %208%%161%%192%%224%%195%%251%%179%%198%: 片式厚膜电阻器; %215%%232%%214%%181%%212%%202%%208%%237%%198%%171%%178%%238%: +/-1%; CODE: 7090798; COMPONENT_HIGH_MAX: 0.4MM; DEVICE: RK73H1ELTP2202F
U7 = RL_8188EUS
U16 U26 = ETA6010_0: DEVICE: ETA6010_SGM2551A
C21 = C_0: %182%%238%%182%%168%%185%%164%%215%%247%%181%%231%%209%%185%(V): 50; %195%%232%%202%%246%: SMD陶瓷电容-50V-100NF-±10%-X7R-0603; %208%%161%%192%%224%%195%%251%%179%%198%: SMD陶瓷电容; CODE: 8070627; COMPONENT_HIGH_MAX: 0.9MM; DEVICE: C1608X7R1H104KT000N
C177 = C_0: %182%%238%%182%%168%%185%%164%%215%%247%%181%%231%%209%%185%(V): 16; %195%%232%%202%%246%: SMD陶瓷电容-16V-100NF-+/-10%-X7R-0402-BT; %208%%161%%192%%224%%195%%251%%179%%198%: SMD陶瓷电容; CODE: 8070614; COMPONENT_HIGH_MAX: 0.6MM; DEVICE: RMEMK105BJ104KV_FR
D3 = IRM-3638A_0: %195%%232%%202%%246%: 红外遥控接收头-5V-0.001A-0.015KM-38KHZ-940NM-7*8*3.75; %208%%161%%192%%224%%195%%251%%179%%198%: 红外遥控接收头; COMPONENT_HIGH_MAX: 6.95MM; DEVICE: TSOP4838
J13 = MMC10S5: %195%%232%%202%%246%: 板卡座类连接器-MICRO-SD卡座-8PIN-PUSH-PUSH-1.1MM-无锁扣-无-1MM-厚度1.45MM-终端专用; CODE: 14240249; COMPONENT_HIGH_MAX: 1.55MM; DEVICE: 5031820832
LED1 = LED2-3_E: %195%%232%%202%%246%: 发光二极管-0.25CD-红绿625NM/570NM-25MA-插装-共阴-终端专用-00500098; CODE: 15020190; COMPONENT_HIGH_MAX: 7.2MM; DEVICE: 209_3SYGSURC_S530_A3HW
Q2 = NPN-BEC_7: %195%%232%%202%%246%: 三极管-NPN-45V-100MA-225MW-200MV@100MA-SOT-23-180@2MA; %208%%161%%192%%224%%195%%251%%179%%198%: 三极管; CODE: 15050206; COMPONENT_HIGH_MAX: 1.26MM; DEVICE: BC847AE6327
Q5 = NPN-BEC_4: %195%%232%%202%%246%: 三极管-NPN-45V-100MA-225MW-200MV@100MA-SOT-23-180@2MA; %208%%161%%192%%224%%195%%251%%179%%198%: 三极管; CODE: 15050206; COMPONENT_HIGH_MAX: 1.26MM; DEVICE: BC847AE6327
Q7 = NPN-BEC_6: %195%%232%%202%%246%: 三极管-NPN-45V-100MA-225MW-200MV@100MA-SOT-23-180@2MA; %208%%161%%192%%224%%195%%251%%179%%198%: 三极管; CODE: 15050206; COMPONENT_HIGH_MAX: 1.26MM; DEVICE: BC847AE6327
Q15 = FETP-GSD_3: %195%%232%%202%%246%: MOSFET-P沟道--8V--3A-50MOHM--8V-SOT23; %208%%161%%192%%224%%195%%251%%179%%198%: MOSFET; CODE: 15060134; COMPONENT_HIGH_MAX: 1.11MM; DEVICE: IRLML6401TR
R22 R31 R34 R129 = R_0: %182%%238%%182%%168%%185%%166%%194%%202%(W): 0.06; %195%%232%%202%%246%: 片式厚膜电阻器-0.0625W-1000OHM-+/-5%-0402-BT; %208%%161%%192%%224%%195%%251%%179%%198%: 片式厚膜电阻器; %215%%232%%214%%181%%212%%202%%208%%237%%198%%171%%178%%238%: +/-5%; CODE: 7090809; COMPONENT_HIGH_MAX: 0.4MM; DEVICE: RC0402JR_071KL
R41 R140 = R_0: %182%%238%%182%%168%%185%%166%%194%%202%(W): 0.06; %195%%232%%202%%246%: 片式厚膜电阻器-0.0625W-10000OHM-+/-5%-0402-BT; %208%%161%%192%%224%%195%%251%%179%%198%: 片式厚膜电阻器; %215%%232%%214%%181%%212%%202%%208%%237%%198%%171%%178%%238%: +/-5%; CODE: 7090815; COMPONENT_HIGH_MAX: 0.4MM; DEVICE: RC_02W103JT
R57 R122 R147 R148 = R_0: %182%%238%%182%%168%%185%%166%%194%%202%(W): 0.06; %195%%232%%202%%246%: 片式厚膜电阻器-0.0625W-4700OHM-+/-5%-0402-BT; %208%%161%%192%%224%%195%%251%%179%%198%: 片式厚膜电阻器; %215%%232%%214%%181%%212%%202%%208%%237%%198%%171%%178%%238%: +/-5%; CODE: 7090793; COMPONENT_HIGH_MAX: 0.4MM; DEVICE: RK73B1ELTP472J
R76 R77 = R_0: %182%%238%%182%%168%%185%%166%%194%%202%(W): 0.1; %195%%232%%202%%246%: 片式厚膜电阻器-0.1W-10000OHM-+/-1%-0603; %208%%161%%192%%224%%195%%251%%179%%198%: 片式厚膜电阻器; %215%%232%%214%%181%%212%%202%%208%%237%%198%%171%%178%%238%: +/-1%; CODE: 7090889; COMPONENT_HIGH_MAX: 0.55MM; DEVICE: RC_03K1002FT
R149 = R_0: %182%%238%%182%%168%%185%%166%%194%%202%(W): 0.1; %195%%232%%202%%246%: 片式厚膜电阻器-0.1W-4700OHM-+/-5%-0603-抗硫化; %208%%161%%192%%224%%195%%251%%179%%198%: 片式厚膜电阻器; %215%%232%%214%%181%%212%%202%%208%%237%%198%%171%%178%%238%: +/-5%; CODE: 7090246; DEVICE: RC0603JR_074K7
R175 = R_0: %182%%238%%182%%168%%185%%166%%194%%202%(W): 0.06; %195%%232%%202%%246%: 片式厚膜电阻器-0.1W-100OHM-±5%-0603; %208%%161%%192%%224%%195%%251%%179%%198%: 片式厚膜电阻器; %215%%232%%214%%181%%212%%202%%208%%237%%198%%171%%178%%238%: ±5%; CODE: 7090269; COMPONENT_HIGH_MAX: 0.55MM; DEVICE: RC0603JR_07100RL
R178 = R_0: %182%%238%%182%%168%%185%%166%%194%%202%(W): 0.06; %195%%232%%202%%246%: 片式厚膜电阻器-0.0625W-75OHM-+/-1%-0402; %208%%161%%192%%224%%195%%251%%179%%198%: 片式厚膜电阻器; %215%%232%%214%%181%%212%%202%%208%%237%%198%%171%%178%%238%: +/-1%; CODE: 7091321; COMPONENT_HIGH_MAX: 0.4MM; DEVICE: RC_02W750FT
R210 = R_0: %182%%238%%182%%168%%185%%166%%194%%202%(W): 0.1; %195%%232%%202%%246%: 片式厚膜电阻器-0.1W-1000OHM-+/-5%-0603; %208%%161%%192%%224%%195%%251%%179%%198%: 片式厚膜电阻器; %215%%232%%214%%181%%212%%202%%208%%237%%198%%171%%178%%238%: +/-5%; CODE: 7090277; COMPONENT_HIGH_MAX: 0.55MM; DEVICE: RC0603JR_071K
S9 = PSW4_A: CODE: 16100051; DEVICE: MS-156

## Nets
1V1_CORE: C19.1(A) C107.1(A) C120.1(A) C121.1(A) C127.1(A) C128.1(A) C189.1(A) C192.1(A) C193.1(A) LB21.1 U10.K14(VDD_1) U10.K15(VDD_2) U10.K16(VDD_3) U10.K17(VDD_4) U10.L14(VDD_5) U10.L15(VDD_6) U10.M14(VDD_7) U10.M15(VDD_8) U10.N14(VDD_9) U10.N15(VDD_10) U10.P14(VDD_11) U10.P15(VDD_12) U10.R11(VDD_13) U10.R14(VDD_14) U10.R15(VDD_15) U10.T11(VDD_16) U10.T14(VDD_17) U10.T15(VDD_18) U10.U11(VDD_19) U10.U12(VDD_20) U10.U13(VDD_21) U10.U14(VDD_22) U10.U15(VDD_23) U10.V11(VDD_24) U10.V12(VDD_25) U10.V13(VDD_26) U10.V14(VDD_27) U10.V15(VDD_28) U10.V16(VDD_29) ; also on sheet 4 7
1V1_CPU: C31.1(A) C132.1(A) C135.1(A) C138.1(A) C242.1(A) C243.1(A) C257.1(A) U10.L21(VDD_CPU_1) U10.M19(VDD_CPU_2) U10.M21(VDD_CPU_3) U10.M22(VDD_CPU_4) U10.N18(VDD_CPU_5) U10.N19(VDD_CPU_6) U10.N22(VDD_CPU_7) U10.P18(VDD_CPU_8) U10.P19(VDD_CPU_9) U10.P22(VDD_CPU_10) U10.R19(VDD_CPU_11) U10.R21(VDD_CPU_12) ; also on sheet 4
1V5_DDR3: C34.1(A) C106.1(A) C203.1(A) C206.1(A) C207.1(A) C208.1(A) C211.1(A) C212.1(A) C213.1(A) C214.1(A) C215.1(A) C216.1(A) C218.1(A) C219.1(A) C220.1(A) C222.1(A) C223.1(A) C227.1(A) C228.1(A) C229.1(A) C230.1(A) C232.1(A) C233.1(A) C237.1(A) C238.1(A) C239.1(A) C240.1(A) C258.1(A) C315.1(A) C319.1(A) R54.1(A) R78.1(A) R158.1(A) R161.1(A) U3.A1(VDDQ1) U3.A8(VDDQ2) U3.B2(VDD1) U3.C1(VDDQ3) U3.C9(VDDQ4) U3.D2(VDDQ5) U3.D9(VDD2) U3.E9(VDDQ6) U3.F1(VDDQ7) U3.G7(VDD3) U3.H2(VDDQ8) U3.H9(VDDQ9) U3.K2(VDD4) U3.K8(VDD5) U3.N1(VDD6) U3.N9(VDD7) U3.R1(VDD8) U3.R9(VDD9) U6.A1(VDDQ1) U6.A8(VDDQ2) U6.B2(VDD1) U6.C1(VDDQ3) U6.C9(VDDQ4) U6.D2(VDDQ5) U6.D9(VDD2) U6.E9(VDDQ6) U6.F1(VDDQ7) U6.G7(VDD3) U6.H2(VDDQ8) U6.H9(VDDQ9) U6.K2(VDD4) U6.K8(VDD5) U6.N1(VDD6) U6.N9(VDD7) U6.R1(VDD8) U6.R9(VDD9) ; also on sheet 4 8
3V3: C13.1(A) C108.1(A) R34.1(A) R41.1(A) R122.1(A) R129.1(A) R140.2(B) R147.1(A) R178.1(A) U10.AD23(DVDD33_STANDBY_1) U10.AD24(DVDD33_STANDBY_2) ; also on sheet 4 5 6 17
3V3_MOS: C15.1(A) C157.1(A) C197.1(A) C198.1(A) C199.1(A) C245.1(A) D14.2(A) LB3.1 LB22.1 Q15.2(S) R77.1(A) R109.1(A) R155.1(A) U10.E13(DVDD33_1) U10.E14(DVDD33_2) U10.E19(DVDD33_3) U10.G5(DVDD33_4) U10.H24(DVDD33_6) U10.K24(DVDD33_7) U10.L24(DVDD33_8) ; also on sheet 5 6 7 8 17 18 19 20 21 22
3V3_MOS_FLASH: C22.1(A) C36.1(A) C47.1(A) C48.1(A) C93.1(A) C142.1(A) C143.1(A) C162.1 C323.1(A) C324.1(A) D14.1(K) R12.1(A) R25.1(A) R29.1(A) R58.1(A) R109.2(B) R111.1(A) R176.1(A) R177.1(A) R188.1(A) R189.1(A) R202.1(A) R203.1(A) R212.1(A) R215.1(A) U19.1(NC1/VDD3) U19.12(VDD1) U19.24(NC15/VDD4) U19.34(NC21/VDDQ1) U19.37(VDD2) U22.AA3(VDD_4) U22.AA5(VDD_5) U22.K6(VDD_1) U22.M6(VDDF_1) U22.N5(VDDF_2) U22.T10(VDDF_3) U22.U9(VDDF_4) U22.W4(VDD_2) U22.Y4(VDD_3)
3V3_SD: C28.1(A) C61.1(A) J13.4(VDD) Q15.3(D) R210.1(A)
3V3_WIFI: C60.1(A) C196.1(A) LB3.2 U7.5(VDD3.3)
5V0_MOS: C50.1(A) C56.1(A) R113.2(B) R220.2(B) U16.1(IN) U26.1(IN) ; also on sheet 5 6 16 19 21 22
AVDD11_PLL012: C12.1(A) C185.1(A) LB21.2 U10.U18(AVDD11_PLL_1) U10.U19(AVDD11_PLL_2)
AVDD33_PLL01: C14.1(A) C141.1(A) LB22.2 U10.W21(AVDD33_PLL_1) U10.Y22(AVDD33_PLL_2)
DVDD11_LDO1_OUT: C255.2(B) U10.AA21(DVDD11_STANDBY_DECAP)
GND: C12.2(B) C13.2(B) C14.2(B) C15.2(B) C19.2(B) C21.2(B) C22.2(B) C28.2(B) C31.2(B) C34.2(B) C36.2(B) C47.2(B) C48.2(B) C49.2(B) C50.2(B) C52.2(B) C56.2(B) C60.2(B) C61.2(B) C62.2(B) C66.2 C93.2(B) C106.2(B) C107.2(B) C108.2(B) C115.2(B) C120.2(B) C121.2(B) C123.2(B) C124.2(B) C127.2(B) C128.2(B) C132.2(B) C135.2(B) C138.2(B) C141.2(B) C142.2(B) C143.2(B) C162.2 C165.2 C177.2(B) C181.2(B) C185.2(B) C189.2(B) C192.2(B) C193.2(B) C196.2(B) C197.2(B) C198.2(B) C199.2(B) C203.2(B) C206.2(B) C211.2(B) C212.2(B) C213.2(B) C214.2(B) C215.2(B) C216.2(B) C218.2(B) C219.2(B) C220.2(B) C227.2(B) C228.2(B) C229.2(B) C230.2(B) C232.2(B) C233.2(B) C237.2(B) C238.2(B) C239.2(B) C240.2(B) C242.2(B) C243.2(B) C245.2(B) C255.1(A) C257.2(B) C258.2(B) C271.2(B) C289.2(B) C308.2(B) C310.2(B) C313.2(B) C314.2(B) C315.2(B) C319.2(B) C323.2(B) C324.2(B) C341.1(A) C342.1(A) C343.1(A) C344.1(A) C353.2(B) C354.2(B) D3.2(GND) D4.2(B) D5.2(B) D10.2(B) D15.2(B) J6.4(GND) J6.5(M1) J6.6(M2) J9.4(GND) J9.5(M1) J9.6(M2) J12.4(GND1) J12.7(GND2) J12.10(S1) J12.11(S2) J13.6(VSS) J13.10(DETECT_TERM) J13.11(S1) J13.12(S2) J13.13(S3) J13.14(S4) J13.15(S5) LED1.2(C) Q2.2(E) Q5.2(E) Q7.2(E) R46.1(A) R57.2(B) R71.1(A) R84.2(B) R89.2(B) R106.1(A) R107.2(B) R111.2(B) R115.1(A) R148.2(B) R149.2(B) R159.2(B) R160.2(B) R210.2(B) S9.2 S9.3 S9.4 U3.A9(VSS1) U3.B1(VSSQ1) U3.B3(VSS2) U3.B9(VSSQ2) U3.D1(VSSQ3) U3.D8(VSSQ4) U3.E1(VSS3) U3.E2(VSSQ5) U3.E8(VSSQ6) U3.F9(VSSQ7) U3.G1(VSSQ8) U3.G8(VSS4) U3.G9(VSSQ9) U3.J2(VSS5) U3.J8(VSS6) U3.M1(VSS7) U3.M9(VSS8) U3.P1(VSS9) U3.P9(VSS10) U3.T1(VSS11) U3.T9(VSS12) U6.A9(VSS1) U6.B1(VSSQ1) U6.B3(VSS2) U6.B9(VSSQ2) U6.D1(VSSQ3) U6.D8(VSSQ4) U6.E1(VSS3) U6.E2(VSSQ5) U6.E8(VSSQ6) U6.F9(VSSQ7) U6.G1(VSSQ8) U6.G8(VSS4) U6.G9(VSSQ9) U6.J2(VSS5) U6.J8(VSS6) U6.M1(VSS7) U6.M9(VSS8) U6.P1(VSS9) U6.P9(VSS10) U6.T1(VSS11) U6.T9(VSS12) U7.2(GND) U10.A1(VSS_1) U10.A2(VSS_2) U10.A3(VSS_3) U10.A28(VSS_123) U10.AA1(VSS_145) U10.AA6(VSS_139) U10.AA18(VSS_146) U10.AA20(VSS_19) U10.AB2(VSS_147) U10.AB5(VSS_148) U10.AB16(VSS_150) U10.AB25(VSS_151) U10.AB27(VSS_199) U10.AC4(VSS_152) U10.AC9(VSS_153) U10.AC10(VSS_224) U10.AC11(VSS_154) U10.AC13(VSS_155) U10.AC14(VSS_225) U10.AC15(VSS_156) U10.AC16(VSS_157) U10.AC24(VSS_158) U10.AD3(VSS_159) U10.AD8(VSS_160) U10.AD9(VSS_161) U10.AD12(VSS_162) U10.AD14(VSS_163) U10.AD16(VSS_164) U10.AD17(VSS_165) U10.AD19(VSS_166) U10.AD22(VSS_37) U10.AD25(VSS_135) U10.AD26(VSS_167) U10.AE1(VSS_168) U10.AE3(VSS_169) U10.AE7(VSS_170) U10.AE8(VSS_171) U10.AE10(VSS_172) U10.AE18(VSS_173) U10.AE19(VSS_174) U10.AE21(VSS_175) U10.AE22(VSS_176) U10.AE23(VSS_177) U10.AE24(VSS_178) U10.AE25(VSS_179) U10.AE26(VSS_192) U10.AF2(VSS_180) U10.AF3(VSS_181) U10.AF4(VSS_182) U10.AF9(VSS_183) U10.AF14(VSS_184) U10.AF15(VSS_185) U10.AF16(VSS_186) U10.AF18(VSS_187) U10.AF19(VSS_188) U10.AF21(VSS_189) U10.AF22(VSS_190) U10.AF25(VSS_191) U10.AG1(VSS_193) U10.AG2(VSS_194) U10.AG5(VSS_195) U10.AG7(VSS_196) U10.AG11(VSS_197) U10.AG13(VSS_198) U10.AG28(VSS_201) U10.AH1(VSS_202) U10.AH2(VSS_203) U10.AH4(VSS_204) U10.AH6(VSS_205) U10.AH10(VSS_206) U10.AH12(VSS_207) U10.AH27(VSS_200) U10.AH28(VSS_208) U10.B2(VSS_4) U10.B3(VSS_5) U10.B14(VSS_6) U10.B26(VSS_7) U10.B27(VSS_20) U10.C3(VSS_209) U10.C14(VSS_8) U10.C19(VSS_9) U10.C20(VSS_10) U10.C26(VSS_65) U10.D14(VSS_11) U10.D19(VSS_12) U10.D20(VSS_13) U10.E2(VSS_211) U10.E4(VSS_14) U10.E11(VSS_15) U10.E12(VSS_16) U10.E20(VSS_17) U10.E21(VSS_18) U10.E25(VSS_212) U10.E26(VSS_213) U10.F1(VSS_36) U10.F3(VSS_21) U10.F4(VSS_22) U10.F5(VSS_23) U10.F25(VSS_214) U10.G4(VSS_24) U10.G13(VSS_25) U10.G14(VSS_26) U10.G21(VSS_27) U10.G24(VSS_28) U10.G25(VSS_29) U10.G26(VSS_215) U10.H1(VSS_216) U10.H2(VSS_210) U10.H4(VSS_30) U10.H5(VSS_226) U10.H13(VSS_31) U10.H14(VSS_32) U10.H21(VSS_33) U10.H22(VSS_34) U10.H25(VSS_35) U10.J3(VSS_38) U10.J4(VSS_39) U10.J5(VSS_149) U10.J21(VSS_40) U10.J22(VSS_41) U10.J24(VSS_42) U10.J25(VSS_217) U10.J26(VSS_43) U10.K3(VSS_44) U10.K13(VSS_45) U10.K18(VSS_46) U10.K19(VSS_47) U10.K21(VSS_48) U10.K22(VSS_49) U10.K25(VSS_50) U10.K26(VSS_117) U10.K27(VSS_218) U10.L1(VSS_51) U10.L2(VSS_52) U10.L3(VSS_53) U10.L4(VSS_54) U10.L5(VSS_55) U10.L11(VSS_56) U10.L12(VSS_57) U10.L13(VSS_58) U10.L16(VSS_59) U10.L17(VSS_60) U10.L18(VSS_61) U10.L19(VSS_62) U10.L22(VSS_63) U10.L25(VSS_64) U10.L26(VSS_220) U10.M3(VSS_66) U10.M4(VSS_67) U10.M5(VSS_68) U10.M6(VSS_69) U10.M11(VSS_70) U10.M12(VSS_71) U10.M13(VSS_72) U10.M16(VSS_73) U10.M17(VSS_74) U10.M18(VSS_75) U10.M24(VSS_76) U10.M25(VSS_219) U10.N3(VSS_77) U10.N6(VSS_107) U10.N11(VSS_78) U10.N12(VSS_79) U10.N13(VSS_80) U10.N16(VSS_81) U10.N17(VSS_82) U10.N24(VSS_83) U10.N25(VSS_84) U10.N26(VSS_221) U10.P2(VSS_85) U10.P6(VSS_86) U10.P11(VSS_87) U10.P12(VSS_88) U10.P13(VSS_89) U10.P16(VSS_90) U10.P17(VSS_91) U10.P24(VSS_92) U10.P25(VSS_93) U10.P26(VSS_94) U10.R1(VSS_95) U10.R3(VSS_96) U10.R5(VSS_97) U10.R9(VSS_99) U10.R12(VSS_100) U10.R13(VSS_101) U10.R16(VSS_102) U10.R17(VSS_103) U10.R18(VSS_104) U10.R22(VSS_105) U10.R24(VSS_106) U10.R26(VSS_108) U10.T3(VSS_109) U10.T4(VSS_110) U10.T6(VSS_98) U10.T12(VSS_111) U10.T13(VSS_112) U10.T16(VSS_113) U10.T17(VSS_114) U10.T18(VSS_115) U10.T19(VSS_116) U10.U6(VSS_118) U10.U9(VSS_119) U10.U16(VSS_120) U10.U17(VSS_121) U10.U21(VSS_122) U10.V2(VSS_124) U10.V3(VSS_125) U10.V5(VSS_126) U10.V6(VSS_127) U10.V9(VSS_128) U10.V17(VSS_129) U10.V18(AVSS_PLL_1) U10.V19(AVSS_PLL_2) U10.V21(AVSS_PLL_3) U10.V24(VSS_130) U10.V25(VSS_131) U10.W1(VSS_132) U10.W5(VSS_133) U10.W6(VSS_222) U10.W22(AVSS_PLL_4) U10.W24(VSS_134) U10.Y2(VSS_136) U10.Y4(VSS_137) U10.Y6(VSS_138) U10.Y10(VSS_140) U10.Y13(VSS_141) U10.Y15(VSS_142) U10.Y21(VSS_143) U10.Y25(VSS_144) U10.Y27(VSS_223) U16.2(GND) U19.2(NC2/VSS3) U19.13(VSS1) U19.23(NC14/VSS4) U19.25(NC16/VSS5) U19.36(VSS2) U19.48(NC29/VSS6) U22.AA4(VSS_8) U22.AA6(VSS_9) U22.K4(VSS_1) U22.M7(VSS_2) U22.P5(VSS_3) U22.R10(VSS_4) U22.U8(VSS_5) U22.Y2(VSS_6) U22.Y5(VSS_7) U26.2(GND) ; also on sheet 3 4 5 6 7 8 16 17 18 19 20 21 22
DDR_ADDR0: U3.N3(A0) U6.N3(A0) ; also on sheet 8
DDR_ADDR1: U3.P7(A1) U6.P7(A1) ; also on sheet 8
DDR_ADDR2: U3.P3(A2) U6.P3(A2) ; also on sheet 8
DDR_ADDR3: U3.N2(A3) U6.N2(A3) ; also on sheet 8
DDR_ADDR4: U3.P8(A4) U6.P8(A4) ; also on sheet 8
DDR_ADDR5: U3.P2(A5) U6.P2(A5) ; also on sheet 8
DDR_ADDR6: U3.R8(A6) U6.R8(A6) ; also on sheet 8
DDR_ADDR7: U3.R2(A7) U6.R2(A7) ; also on sheet 8
DDR_ADDR8: U3.T8(A8) U6.T8(A8) ; also on sheet 8
DDR_ADDR9: U3.R3(A9) U6.R3(A9) ; also on sheet 8
DDR_ADDR10: U3.L7(A10/AP) U6.L7(A10/AP) ; also on sheet 8
DDR_ADDR11: U3.R7(A11) U6.R7(A11) ; also on sheet 8
DDR_ADDR12: U3.N7(A12/BC~) U6.N7(A12/BC~) ; also on sheet 8
DDR_ADDR13: U3.T3(A13) U6.T3(A13) ; also on sheet 8
DDR_ADDR14: U3.T7(A14) U6.T7(A14) ; also on sheet 8
DDR_ADDR15: U3.M7(NC5) U6.M7(NC5) ; also on sheet 8
DDR_BA0: U3.M2(BA0) U6.M2(BA0) ; also on sheet 8
DDR_BA1: U3.N8(BA1) U6.N8(BA1) ; also on sheet 8
DDR_BA2: U3.M3(BA2) U6.M3(BA2) ; also on sheet 8
DDR_CASN: U3.K3(~{CAS}) U6.K3(~{CAS}) ; also on sheet 8
DDR_CKE: U3.K9(CKE) U6.K9(CKE) ; also on sheet 8
DDR_CLK1N: R11.2(B) R15.2(B) U3.K7(~{CK}) U6.K7(~{CK}) ; also on sheet 8
DDR_CLK1P: R11.1(A) R15.1(A) U3.J7(CK) U6.J7(CK) ; also on sheet 8
DDR_CSN: U3.L2(~{CS}) U6.L2(~{CS}) ; also on sheet 8
DDR_DM0: U3.E7(LDM) ; also on sheet 8
DDR_DM1: U3.D3(UDM) ; also on sheet 8
DDR_DM2: U6.E7(LDM) ; also on sheet 8
DDR_DM3: U6.D3(UDM) ; also on sheet 8
DDR_DQ0: U3.E3(DQ0) ; also on sheet 8
DDR_DQ1: U3.F7(DQ1) ; also on sheet 8
DDR_DQ2: U3.F2(DQ2) ; also on sheet 8
DDR_DQ3: U3.F8(DQ3) ; also on sheet 8
DDR_DQ4: U3.H3(DQ4) ; also on sheet 8
DDR_DQ5: U3.H8(DQ5) ; also on sheet 8
DDR_DQ6: U3.G2(DQ6) ; also on sheet 8
DDR_DQ7: U3.H7(DQ7) ; also on sheet 8
DDR_DQ8: U3.D7(DQ8) ; also on sheet 8
DDR_DQ9: U3.C3(DQ9) ; also on sheet 8
DDR_DQ10: U3.C8(DQ10) ; also on sheet 8
DDR_DQ11: U3.C2(DQ11) ; also on sheet 8
DDR_DQ12: U3.A7(DQ12) ; also on sheet 8
DDR_DQ13: U3.A2(DQ13) ; also on sheet 8
DDR_DQ14: U3.B8(DQ14) ; also on sheet 8
DDR_DQ15: U3.A3(DQ15) ; also on sheet 8
DDR_DQ16: U6.E3(DQ0) ; also on sheet 8
DDR_DQ17: U6.F7(DQ1) ; also on sheet 8
DDR_DQ18: U6.F2(DQ2) ; also on sheet 8
DDR_DQ19: U6.F8(DQ3) ; also on sheet 8
DDR_DQ20: U6.H3(DQ4) ; also on sheet 8
DDR_DQ21: U6.H8(DQ5) ; also on sheet 8
DDR_DQ22: U6.G2(DQ6) ; also on sheet 8
DDR_DQ23: U6.H7(DQ7) ; also on sheet 8
DDR_DQ24: U6.D7(DQ8) ; also on sheet 8
DDR_DQ25: U6.C3(DQ9) ; also on sheet 8
DDR_DQ26: U6.C8(DQ10) ; also on sheet 8
DDR_DQ27: U6.C2(DQ11) ; also on sheet 8
DDR_DQ28: U6.A7(DQ12) ; also on sheet 8
DDR_DQ29: U6.A2(DQ13) ; also on sheet 8
DDR_DQ30: U6.B8(DQ14) ; also on sheet 8
DDR_DQ31: U6.A3(DQ15) ; also on sheet 8
DDR_DQS0N: U3.G3(~{LDQS}) ; also on sheet 8
DDR_DQS0P: U3.F3(LDQS) ; also on sheet 8
DDR_DQS1N: U3.B7(~{UDQS}) ; also on sheet 8
DDR_DQS1P: U3.C7(UDQS) ; also on sheet 8
DDR_DQS2N: U6.G3(~{LDQS}) ; also on sheet 8
DDR_DQS2P: U6.F3(LDQS) ; also on sheet 8
DDR_DQS3N: U6.B7(~{UDQS}) ; also on sheet 8
DDR_DQS3P: U6.C7(UDQS) ; also on sheet 8
DDR_ODT: U3.K1(ODT) U6.K1(ODT) ; also on sheet 8
DDR_RASN: U3.J3(~{RAS}) U6.J3(~{RAS}) ; also on sheet 8
DDR_RESETN: C313.1(A) C314.1(A) U3.T2(~{RESET}) U6.T2(~{RESET}) ; also on sheet 8
DDR_VREF_CA_A: C207.2(B) C289.1(A) R158.2(B) R159.1(A) U3.M8(VREFCA)
DDR_VREF_CA_B: C222.2(B) C310.1(A) R107.1(A) R161.2(B) U6.M8(VREFCA)
DDR_VREF_DQ_A: C208.2(B) C271.1(A) R54.2(B) R160.1(A) U3.H1(VREFDQ)
DDR_VREF_DQ_B: C223.2(B) C308.1(A) R78.2(B) R84.1(A) U6.H1(VREFDQ)
DDR_WEN: U3.L3(~{WE}) U6.L3(~{WE}) ; also on sheet 8
IR_IN: D3.1(OUT) R140.1(A) ; also on sheet 6
LED_CLK: R22.1(A) R57.1(A) R147.2(B) ; also on sheet 6
LED_DATA: R31.1(A) R122.2(B) R148.1(A) ; also on sheet 6
LED_KEY0: C21.1(A) R41.2(B) S9.1 ; also on sheet 6
NF_ALE_EMMC_PWREN: U19.17(ALE) ; also on sheet 6
NF_CLE: U19.16(CLE) ; also on sheet 6
NF_CSN0_EMMC_CMD: R212.2(B) U19.9(~{CE}) U22.W5(CMD) ; also on sheet 6
NF_DQ0_EMMC_D0: R189.2(B) U19.29(I/O0) U22.H3(DAT0) ; also on sheet 6
NF_DQ1_EMMC_D1: R12.2(B) U19.30(I/O1) U22.H4(DAT1) ; also on sheet 6
NF_DQ2_EMMC_D2: R29.2(B) U19.31(I/O2) U22.H5(DAT2) ; also on sheet 6
NF_DQ3_EMMC_D3: R58.2(B) U19.32(I/O3) U22.J2(DAT3) ; also on sheet 6
NF_DQ4_EMMC_D4: R176.2(B) U19.41(I/O4) U22.J3(DAT4) ; also on sheet 6
NF_DQ5_EMMC_D5: R177.2(B) U19.42(I/O5) U22.J4(DAT5) ; also on sheet 6
NF_DQ6_EMMC_D6: R188.2(B) U19.43(I/O6) U22.J5(DAT6) ; also on sheet 6
NF_DQ7_EMMC_D7_BOOT_SEL0: R202.2(B) U19.44(I/O7) U22.J6(DAT7) ; also on sheet 6
NF_RDY0_EMMC_RST: C115.1(A) R203.2(B) U19.7(R/B~) U22.U5(RSTN) ; also on sheet 6
NF_REN_EMMC_CLK: U19.8(~{RE}) U22.W6(CLK) ; also on sheet 6
NF_WEN_EMMC_DET: U19.18(~{WE}) ; also on sheet 6
NF_WP: R89.1(A) R215.2(B) U19.19(~{WP})
SDIO0_CARD_DETECT: J13.9(SWITCH_TERM) R155.2(B) ; also on sheet 6
SDIO0_CCLK_OUT: J13.5(CLK) ; also on sheet 6
SDIO0_CCMD: J13.3(CMD) R153.2(B) ; also on sheet 6
SDIO0_CDATA0: J13.7(DAT0) R152.2(B) ; also on sheet 6
SDIO0_CDATA1: J13.8(DAT1) R151.2(B) ; also on sheet 6
SDIO0_CDATA2: J13.1(DATA2) R154.2(B) ; also on sheet 6
SDIO0_CDATA3: J13.2(CD/DAT3) R156.2(B) ; also on sheet 6
SDIO0_PWREN: R76.1(A) R149.1(A) ; also on sheet 6
SDIO_3318: C62.1(A) R151.1(A) R152.1(A) R153.1(A) R154.1(A) R156.1(A) ; also on sheet 6
USB0_DM: C341.2(B) D5.1(A) J6.2(D-) ; also on sheet 7
USB0_DP: C342.2(B) D4.1(A) J6.3(D+) ; also on sheet 7
USB1_DM: C343.2(B) D10.1(A) J9.2(D-) ; also on sheet 7
USB1_DP: C344.2(B) D15.1(A) J9.3(D+) ; also on sheet 7
USB01_VBUS: C49.1(A) C165.1 C353.1(A) C354.1(A) J6.1(VBUS) J9.1(VBUS) U26.5(OUT)
USB2_DM: U7.4(DM) ; also on sheet 7
USB2_DP: U7.3(DP) ; also on sheet 7
USB3_DM: J12.2(D-) ; also on sheet 7
USB3_DP: J12.3(D+) ; also on sheet 7
USB3_RXN: J12.5(RX-) ; also on sheet 7
USB3_RXP: J12.6(RX+) ; also on sheet 7
USB3_TXN: C129.2(B) ; also on sheet 7
USB3_TXP: C70.2(B) ; also on sheet 7
N08138: LED1.3(A2) Q7.3(C) R129.2(B)
N08150: LED1.1(A1) Q2.3(C) R34.2(B)
N08162: C177.1(A) C181.1(A) D3.3(VCC) R178.2(B)
N08276: Q5.1(B) R76.2(B)
N08280: Q5.3(C) R175.2(B)
N08284: C157.2(B) Q15.1(G) R77.2(B) R175.1(A)
N08368: Q7.1(B) R22.2(B)
N08382: Q2.1(B) R31.2(B)
N09194: C129.1(A) J12.8(TX-)
N09198: C52.1(A) C66.1 J12.1(VBUS) U16.5(OUT)
N09242: R106.2(B) U26.4(ILIM)
N09248: R115.2(B) U16.4(ILIM)
N09254: R113.1(A) U16.3(EN)
N09262: R220.1(A) U26.3(EN)
N09266: C70.1(A) J12.9(TX+)
N10813: C123.1(A) C124.1(A) U22.K2(VDDI)
N10839: R25.2(B) U19.38(NC23/VDDQ2)
N12139: R71.2(B) U6.L8(ZQ)
N13470: R46.2(B) U3.L8(ZQ)

Not connected (* = marked no-connect by the designer): U3 J1(NC1) J9(NC2) L1(NC3) L9(NC4); U6 J1(NC1) J9(NC2) L1(NC3) L9(NC4); U7 1(LED) 6(WPS); U19 3(NC3) 4(NC4) 5(NC5) 6(NC6) 10(NC7) 11(NC8) 14(NC9) 15(NC10) 20(NC11) 21(NC12) 22(NC13) 26(NC17) 27(NC18) 28(NC19) 33(NC20) 35(NC22) 39(NC24) 40(NC25) 45(NC26) 46(NC27) 47(NC28); U22 A4(NC_1) A6(NC_2) A9(NC_3) A11(NC_4) AA1(NC_122) AA2(NC_123) AA7(NC_124) AA8(NC_125) AA9(NC_126) AA10(NC_127) AA11(NC_128) AA12(NC_129) AA13(NC_130) AA14(NC_131) AE1(NC_132) AE14(NC_133) AG2(NC_134) AG13(NC_135) AH4(NC_136) AH6(NC_137) AH9(NC_138) AH11(NC_95) B2(NC_5) B13(NC_6) D1(NC_7) D14(NC_8) H1(NC_9) H2(NC_10) H6(NC_11) H7(NC_12) H8(NC_13) H9(NC_14) H10(NC_15) H11(NC_16) H12(NC_17) H13(NC_18) H14(NC_19) J1(NC_20) J7(NC_21) J8(NC_22) J9(NC_23) J10(NC_24) J11(NC_25) J12(NC_26) J13(NC_27) J14(NC_28) K1(NC_29) K3(NC_30) K5(NC_31) K7(NC_32) K8(NC_33) K9(NC_34) K10(NC_35) K11(NC_36) K12(NC_37) K13(NC_38) K14(NC_39) L1(NC_40) L2(NC_41) L3(NC_42) L4(A1) L12(NC_43) L13(NC_44) L14(NC_45) M1(NC_46) M2(NC_47) M3(NC_48) M5(NC_49) M8(NC_50) M9(NC_51) M10(NC_52) M12(NC_53) M13(NC_54) M14(NC_55) N1(NC_56) N2(NC_57) N3(NC_58) N10(NC_59) N12(NC_60) N13(NC_61) N14(NC_62) P1(NC_63) P2(NC_64) P3(NC_65) P10(NC_66) P12(NC_67) P13(NC_68) P14(NC_69) R1(NC_70) R2(NC_71) R3(NC_72) R5(NC_73) R12(NC_74) R13(NC_75) R14(NC_76) T1(NC_77) T2(NC_78) T3(NC_79) T5(NC_80) T12(NC_81) T13(NC_82) T14(NC_83) U1(NC_84) U2(NC_85) U3(NC_86) U6(NC_87) U7(NC_88) U10(NC_89) U12(NC_90) U13(NC_91) U14(NC_92) V1(NC_93) V2(NC_94) V3(NC_96) V12(NC_97) V13(NC_98) V14(NC_99) W1(NC_100) W2(NC_101) W3(NC_102) W7(NC_103) W8(NC_104) W9(NC_105) W10(NC_106) W11(NC_107) W12(NC_108) W13(NC_109) W14(NC_110) Y1(NC_111) Y3(NC_112) Y6(NC_113) Y7(NC_114) Y8(NC_115) Y9(NC_116) Y10(NC_117) Y11(NC_118) Y12(NC_119) Y13(NC_120) Y14(NC_121)

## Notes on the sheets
sheet 9
- Unit 4 of Hi3798MV100(POWER)
sheet 11
- DDRA
- 1%
- 1%
- 1%
- 1%
- 1%
sheet 12
- DDRB
- 1%
- 1%
- 1%
- 1%
- 1%
sheet 13
- NAND FLASH/EMMC
- eMMC
- NAND FLASH
- H6 eMMC5.0
- 4GB
- NFWP
- 0:Protect
- 1:NOT Protect
- 4GB
- If use micron nand flash,R25=NC
- T5 eMMC5.0
- R5 eMMC5.0
- Only For MLC NAND
sheet 14
- USB
- USB0:usb_boot/adb
- 39/(22+3)=1.56A
- USB1
- WiFi 1T1R 2.4G
- 39/(22+3)=1.56A
- USB3.0
sheet 15
- SD CARD
- S
- D
- G
- LED
- IR
- R ON+G OFF->STBY
- R OFF+G ON->WORK
- R OFF+G OFF->NO POWER
